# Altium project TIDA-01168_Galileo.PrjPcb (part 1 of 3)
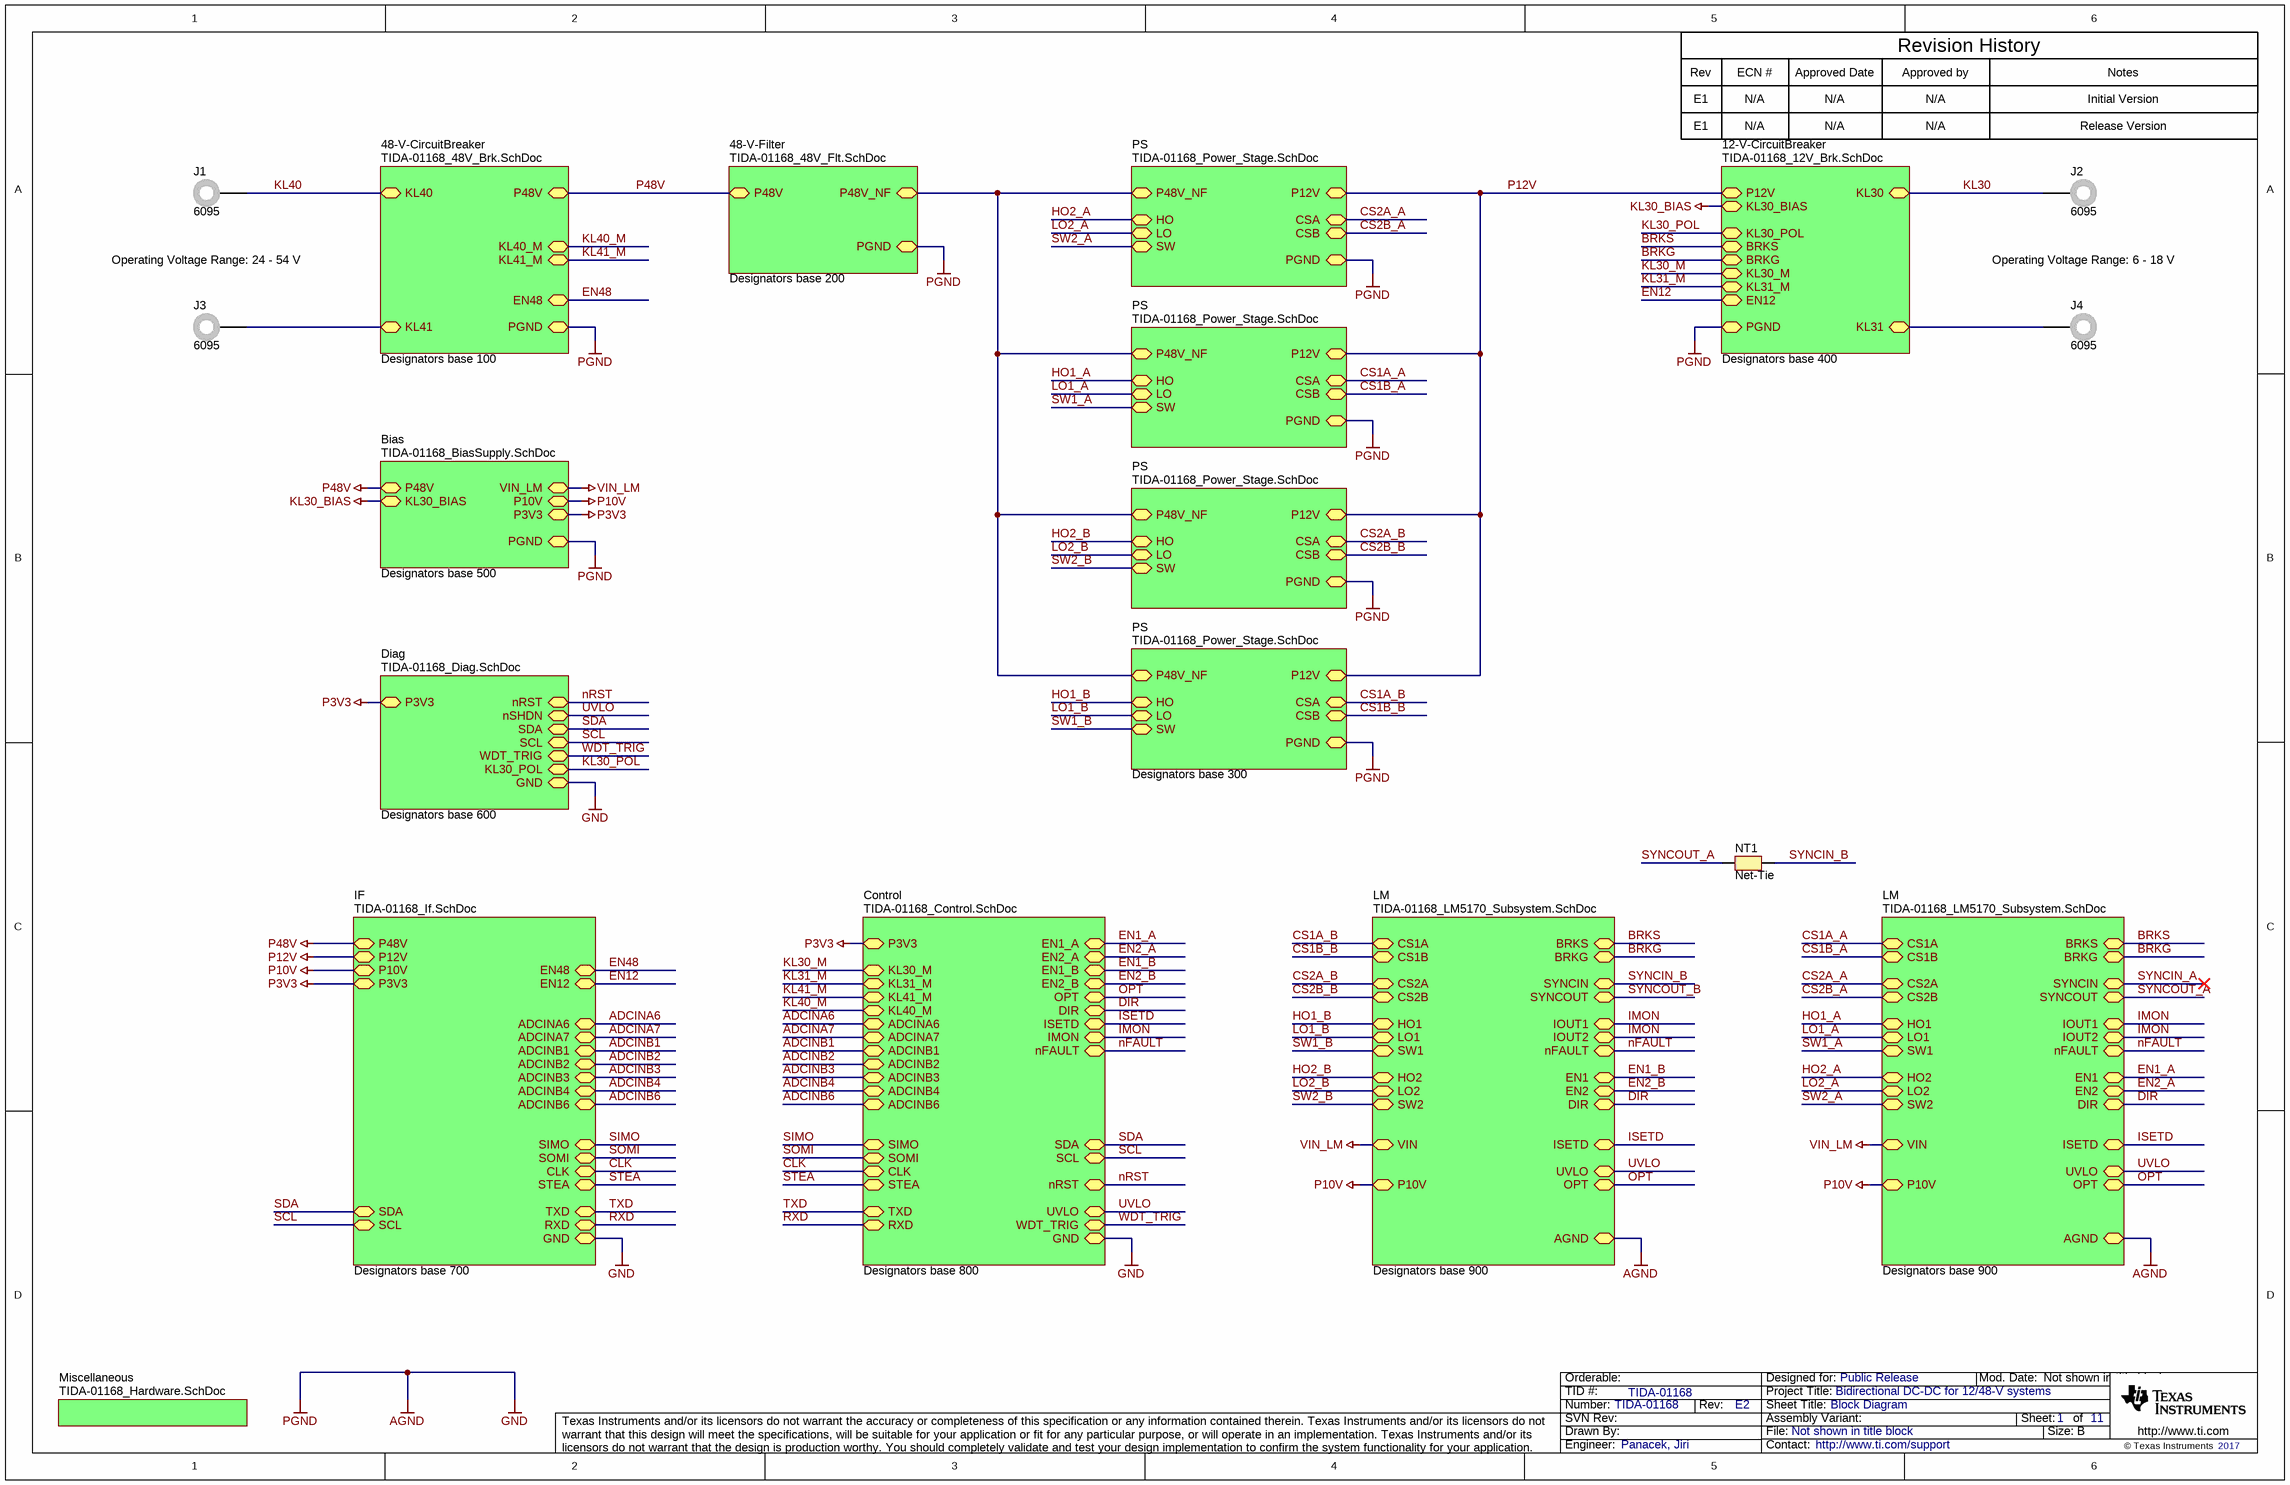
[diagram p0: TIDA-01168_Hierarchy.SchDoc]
CopyrightYear: 2017; PCB_Layout: Panacek, Jiri; PCB_Rev: E2; PRJ_Customer: Public Release; PRJ_Engineer: Panacek, Jiri; PRJ_Number: TIDA-01168; PRJ_Title: Bidirectional DC-DC for 12/48-V systems; SCH_Rev: E2; TechSupport: http://www.ti.com/support; TID: TIDA-01168
11 sheets, 477 parts. Net scope: hierarchical (ports join the sheet entries above them; power ports are global).
Board file: TIDA-01168_PCB.PcbDoc
Sheets:
  TIDA-01168_Hierarchy.SchDoc
    PS = TIDA-01168_Power_Stage.SchDoc
    Miscellaneous = TIDA-01168_Hardware.SchDoc
    48-V-CircuitBreaker = TIDA-01168_48V_Brk.SchDoc
    12-V-CircuitBreaker = TIDA-01168_12V_Brk.SchDoc
    Diag = TIDA-01168_Diag.SchDoc
    Control = TIDA-01168_Control.SchDoc
    LM = TIDA-01168_LM5170_Subsystem.SchDoc
    Bias = TIDA-01168_BiasSupply.SchDoc
    PS = TIDA-01168_Power_Stage.SchDoc
    PS = TIDA-01168_Power_Stage.SchDoc
    PS = TIDA-01168_Power_Stage.SchDoc
    LM = TIDA-01168_LM5170_Subsystem.SchDoc
    IF = TIDA-01168_If.SchDoc
    48-V-Filter = TIDA-01168_48V_Flt.SchDoc

## Sheet TIDA-01168_Hierarchy.SchDoc: Block Diagram
size 431 x 279 mm; Date: Not shown in title block; ApprovedBy: Not shown in title block; CheckedBy: Not shown in title block; Author: Not shown in title block; CompanyName: Not shown in title block; Engineer: Not shown in title block; Organization: Not shown in title block; Address1: Not shown in title block; Address2: Not shown in title block; Address3: Not shown in title block; Address4: Not shown in title block; DocumentNumber: 1; Revision: Use project parameter SCH_Rev; SheetNumber: 1; SheetTotal: 11; PageSetup: Record=PageOptions¦CenterHorizontal=True¦CenterVertical=True¦PrintScale=0.64¦XCorrection=1.00¦YCorrection=1.00¦PrintKind=0¦BorderSize=5000000¦LeftOffset=0¦BottomOffset=0¦Orientation=2¦PaperLength=1000¦PaperWidth=1000¦Scale=100¦PaperSource=15¦PrintQuality=600¦MediaType=1¦DitherType=10¦PrintScaleMode=1¦PaperKind=Letter

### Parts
J1  6095  [Keystone_6095]
J2  6095  [Keystone_6095]
J3  6095  [Keystone_6095]
J4  6095  [Keystone_6095]
NT1  Net-Tie  [Net-Tie_10mil]  (net tie, no BOM)

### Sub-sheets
12-V-CircuitBreaker = TIDA-01168_12V_Brk.SchDoc: P12V, PGND, KL31, KL30, BRKS, BRKG, KL30_BIAS, EN12, KL30_POL, KL30_M, KL31_M
48-V-CircuitBreaker = TIDA-01168_48V_Brk.SchDoc: KL40, KL41, PGND, P48V, EN48, KL40_M, KL41_M
48-V-Filter = TIDA-01168_48V_Flt.SchDoc: P48V_NF, P48V, PGND
Bias = TIDA-01168_BiasSupply.SchDoc: P48V, KL30_BIAS, VIN_LM, P3V3, P10V, PGND
Control = TIDA-01168_Control.SchDoc: SCL, SDA, EN1_A, EN2_A, EN1_B, EN2_B, OPT, DIR, ISETD, IMON, nFAULT, TXD, RXD, P3V3, nRST, GND, UVLO, WDT_TRIG, ADCINA6, ADCINA7, ADCINB1, ADCINB2, ADCINB3, ADCINB4, ADCINB6, SIMO, SOMI, CLK, STEA, KL41_M, KL40_M, KL31_M, KL30_M
Diag = TIDA-01168_Diag.SchDoc: SCL, SDA, nRST, P3V3, GND, KL30_POL, nSHDN, WDT_TRIG
IF = TIDA-01168_If.SchDoc: EN48, EN12, TXD, RXD, GND, P3V3, STEA, CLK, SOMI, SIMO, ADCINB6, ADCINB4, ADCINB3, ADCINB2, ADCINB1, ADCINA7, ADCINA6, SDA, SCL, P48V, P12V, P10V
LM = TIDA-01168_LM5170_Subsystem.SchDoc: CS1A, CS1B, HO1, SW2, SW1, BRKS, BRKG, UVLO, VIN, nFAULT, IOUT2, IOUT1, EN2, EN1, SYNCOUT, SYNCIN, ISETD, DIR, AGND, CS2A, CS2B, HO2, LO1, LO2, P10V, OPT
LM = TIDA-01168_LM5170_Subsystem.SchDoc: CS1A, CS1B, HO1, SW2, SW1, BRKS, BRKG, UVLO, VIN, nFAULT, IOUT2, IOUT1, EN2, EN1, SYNCOUT, SYNCIN, ISETD, DIR, AGND, CS2A, CS2B, HO2, LO1, LO2, P10V, OPT
Miscellaneous = TIDA-01168_Hardware.SchDoc: no entries
PS = TIDA-01168_Power_Stage.SchDoc: P48V_NF, P12V, PGND, HO, CSA, LO, SW, CSB
PS = TIDA-01168_Power_Stage.SchDoc: P48V_NF, P12V, PGND, HO, CSA, LO, SW, CSB
PS = TIDA-01168_Power_Stage.SchDoc: P48V_NF, P12V, PGND, HO, CSA, LO, SW, CSB
PS = TIDA-01168_Power_Stage.SchDoc: P48V_NF, P12V, PGND, HO, CSA, LO, SW, CSB

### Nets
CS1B_A: sheet PS/P12V, sheet PS/CSB, sheet 12-V-CircuitBreaker/P12V, sheet LM/CS1B, sheet LM/CS2B, sheet PS/P12V, sheet PS/CSB, sheet PS/P12V, sheet PS/CSB, sheet PS/P12V, sheet PS/CSB, sheet LM/CS1B, sheet LM/CS2B, sheet IF/P12V  [also labelled CS1B_B, CS2B_A, CS2B_B, P12V]
GND: J3.1 J4.1 ; sheet PS/PGND, sheet 48-V-CircuitBreaker/KL41, sheet 48-V-CircuitBreaker/PGND, sheet 12-V-CircuitBreaker/PGND, sheet 12-V-CircuitBreaker/KL31, sheet Diag/GND, sheet Control/GND, sheet LM/AGND, sheet Bias/PGND, sheet PS/PGND, sheet PS/PGND, sheet PS/PGND, sheet LM/AGND, sheet IF/GND, sheet 48-V-Filter/PGND  [also labelled AGND, PGND]
KL30_BIAS: sheet 12-V-CircuitBreaker/KL30_BIAS, sheet Bias/KL30_BIAS
P3V3: sheet Diag/P3V3, sheet Control/P3V3, sheet Bias/P3V3, sheet IF/P3V3
P10V: sheet LM/P10V, sheet Bias/P10V, sheet LM/P10V, sheet IF/P10V
P48V: sheet 48-V-CircuitBreaker/P48V, sheet Bias/P48V, sheet IF/P48V, sheet 48-V-Filter/P48V
VIN_LM: sheet LM/VIN, sheet Bias/VIN_LM, sheet LM/VIN
ADCINA6: sheet Control/ADCINA6, sheet IF/ADCINA6
ADCINA7: sheet Control/ADCINA7, sheet IF/ADCINA7
ADCINB1: sheet Control/ADCINB1, sheet IF/ADCINB1
ADCINB2: sheet Control/ADCINB2, sheet IF/ADCINB2
ADCINB3: sheet Control/ADCINB3, sheet IF/ADCINB3
ADCINB4: sheet Control/ADCINB4, sheet IF/ADCINB4
ADCINB6: sheet Control/ADCINB6, sheet IF/ADCINB6
BRKG: sheet 12-V-CircuitBreaker/BRKG, sheet LM/BRKG, sheet LM/BRKG
BRKS: sheet 12-V-CircuitBreaker/BRKS, sheet LM/BRKS, sheet LM/BRKS
CLK: sheet Control/CLK, sheet IF/CLK
CS1A_A: sheet LM/CS1A, sheet PS/CSA
CS1A_B: sheet PS/CSA, sheet LM/CS1A
CS2A_A: sheet PS/CSA, sheet LM/CS2A
CS2A_B: sheet PS/CSA, sheet LM/CS2A
DIR: sheet Control/DIR, sheet LM/DIR, sheet LM/DIR
EN1_A: sheet Control/EN1_A, sheet LM/EN1  [project net EN1]
EN1_B: sheet Control/EN1_B, sheet LM/EN1  [project net EN1]
EN2_A: sheet Control/EN2_A, sheet LM/EN2  [project net EN2]
EN2_B: sheet Control/EN2_B, sheet LM/EN2  [project net EN2]
EN12: sheet 12-V-CircuitBreaker/EN12, sheet IF/EN12
EN48: sheet 48-V-CircuitBreaker/EN48, sheet IF/EN48
HO1_A: sheet LM/HO1, sheet PS/HO
HO1_B: sheet PS/HO, sheet LM/HO1
HO2_A: sheet PS/HO, sheet LM/HO2
HO2_B: sheet PS/HO, sheet LM/HO2
IMON: sheet Control/IMON, sheet LM/IOUT2, sheet LM/IOUT1, sheet LM/IOUT2, sheet LM/IOUT1
ISETD: sheet Control/ISETD, sheet LM/ISETD, sheet LM/ISETD
KL30: J2.1 ; sheet 12-V-CircuitBreaker/KL30
KL30_M: sheet 12-V-CircuitBreaker/KL30_M, sheet Control/KL30_M
KL30_POL: sheet 12-V-CircuitBreaker/KL30_POL, sheet Diag/KL30_POL
KL31_M: sheet 12-V-CircuitBreaker/KL31_M, sheet Control/KL31_M
KL40: J1.1 ; sheet 48-V-CircuitBreaker/KL40
KL40_M: sheet 48-V-CircuitBreaker/KL40_M, sheet Control/KL40_M
KL41_M: sheet 48-V-CircuitBreaker/KL41_M, sheet Control/KL41_M
LO1_A: sheet LM/LO1, sheet PS/LO
LO1_B: sheet PS/LO, sheet LM/LO1
LO2_A: sheet PS/LO, sheet LM/LO2
LO2_B: sheet PS/LO, sheet LM/LO2
nFAULT: sheet Control/nFAULT, sheet LM/nFAULT, sheet LM/nFAULT
nRST: sheet Diag/nRST, sheet Control/nRST
OPT: sheet Control/OPT, sheet LM/OPT, sheet LM/OPT
P48V_NF: sheet PS/P48V_NF, sheet PS/P48V_NF, sheet PS/P48V_NF, sheet PS/P48V_NF, sheet 48-V-Filter/P48V_NF
RXD: sheet Control/RXD, sheet IF/RXD
SCL: sheet Diag/SCL, sheet Control/SCL, sheet IF/SCL
SDA: sheet Diag/SDA, sheet Control/SDA, sheet IF/SDA
SIMO: sheet Control/SIMO, sheet IF/SIMO
SOMI: sheet Control/SOMI, sheet IF/SOMI
STEA: sheet Control/STEA, sheet IF/STEA
SW1_A: sheet LM/SW1, sheet PS/SW
SW1_B: sheet PS/SW, sheet LM/SW1
SW2_A: sheet PS/SW, sheet LM/SW2
SW2_B: sheet PS/SW, sheet LM/SW2
SYNCIN_B: NT1.2 ; sheet LM/SYNCIN
SYNCOUT_A: NT1.1 ; sheet LM/SYNCOUT
TXD: sheet Control/TXD, sheet IF/TXD
UVLO: sheet Diag/nSHDN, sheet Control/UVLO, sheet LM/UVLO, sheet LM/UVLO
WDT_TRIG: sheet Diag/WDT_TRIG, sheet Control/WDT_TRIG

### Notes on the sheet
- Rev
- E1
- ECN #
- N/A
- Approved Date
- Approved by
- Revision History
- Notes
- Initial Version
- Release Version
- Operating Voltage Range: 24 - 54 V
- Designators base 200
- Operating Voltage Range: 6 - 18 V
- Designators base 100
- Designators base 400
- Designators base 500
- Designators base 600
- Designators base 300
- Designators base 700
- Designators base 800
- Designators base 900

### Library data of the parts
J1-J4 = 6095: Standard Banana Jack, Uninsulated; Manufacturer: Keystone; CompType: Connector; SymbolCreator: a0412235
NT1 = Net-Tie: Single point connection between nets.; SymbolCreator: codlsc

## Sheet TIDA-01168_Power_Stage.SchDoc: Power Stage
size 431 x 279 mm; Date: Not shown in title block; ApprovedBy: Not shown in title block; CheckedBy: Not shown in title block; Author: Not shown in title block; CompanyName: Not shown in title block; Engineer: Not shown in title block; Organization: Not shown in title block; Address1: Not shown in title block; Address2: Not shown in title block; Address3: Not shown in title block; Address4: Not shown in title block; DocumentNumber: 4; Revision: Use project parameter SCH_Rev; SheetNumber: 4; SheetTotal: 11; PageSetup: Record=PageOptions¦CenterHorizontal=True¦CenterVertical=True¦PrintScale=0.62¦XCorrection=1.00¦YCorrection=1.00¦PrintKind=0¦BorderSize=5000000¦LeftOffset=0¦BottomOffset=0¦Orientation=2¦PaperLength=1000¦PaperWidth=1000¦Scale=100¦PaperSource=15¦PrintQuality=600¦MediaType=1¦DitherType=10¦PrintScaleMode=1¦PaperKind=Letter
Used 4 times, as channels PS, PS, PS, PS. Parts and nets are listed once, with the designators drawn on the sheet.
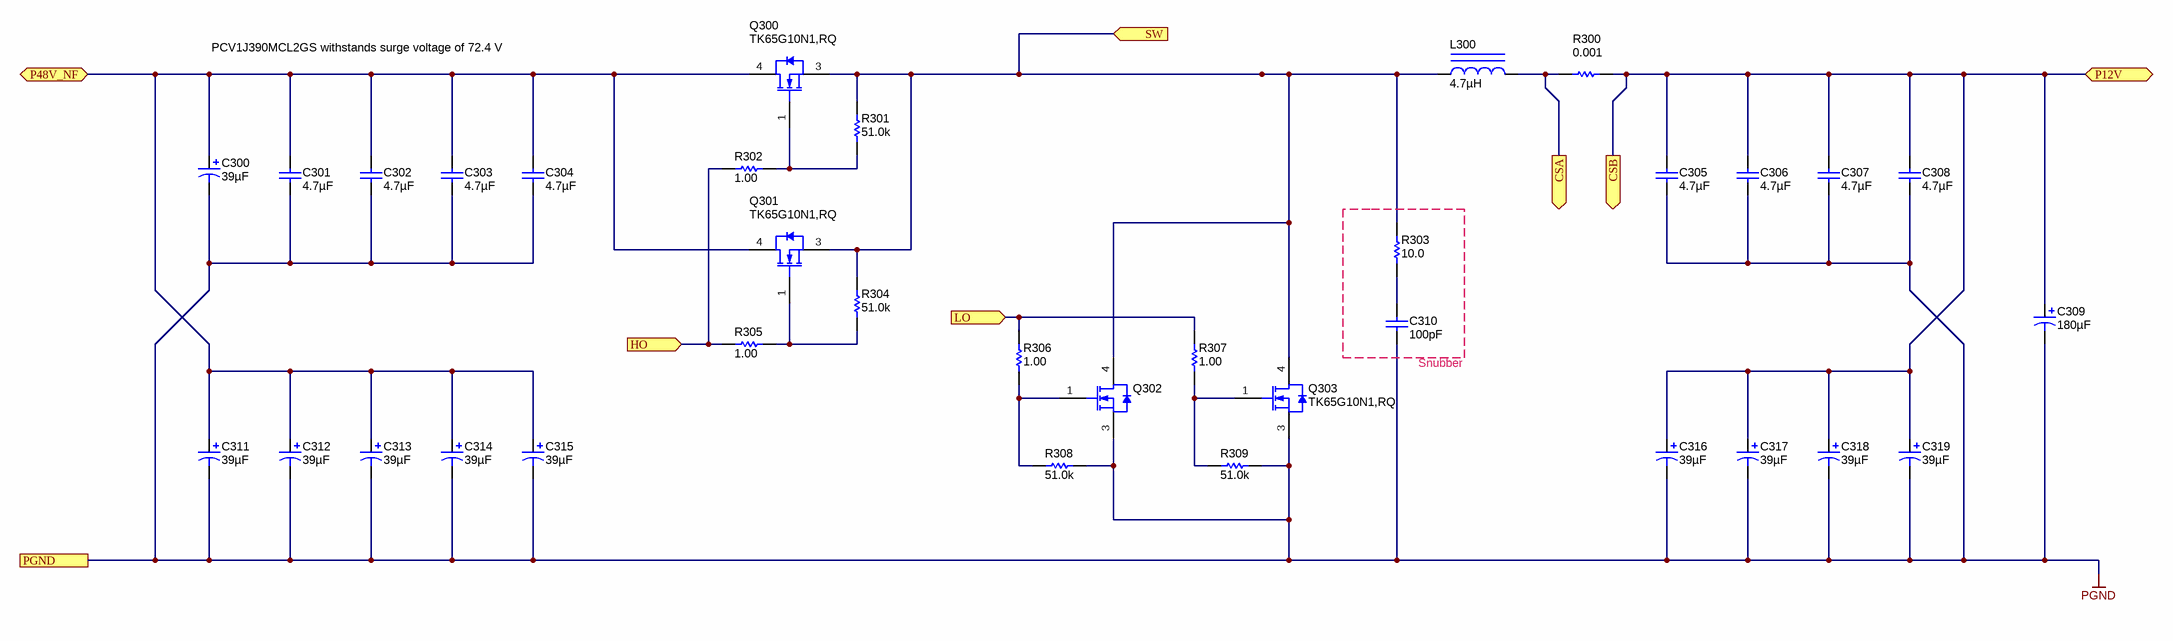
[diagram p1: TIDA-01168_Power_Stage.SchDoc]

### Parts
C300  ValueDisplayed: 39µF  [PCV_800x1200]  (hidden comment: PCV1J390MCL2GS)
C301  ValueDisplayed: 4.7µF  [2220_250]  (hidden comment: CGA9N2X7R2A475M230KA)
C302  ValueDisplayed: 4.7µF  [2220_250]  (hidden comment: CGA9N2X7R2A475M230KA)
C303  ValueDisplayed: 4.7µF  [2220_250]  (hidden comment: CGA9N2X7R2A475M230KA)
C304  ValueDisplayed: 4.7µF  [2220_250]  (hidden comment: CGA9N2X7R2A475M230KA)
C305  ValueDisplayed: 4.7µF  [2220_250]  (hidden comment: CGA9N2X7R2A475M230KA)
C306  ValueDisplayed: 4.7µF  [2220_250]  (hidden comment: CGA9N2X7R2A475M230KA)
C307  ValueDisplayed: 4.7µF  [2220_250]  (hidden comment: CGA9N2X7R2A475M230KA)
C308  ValueDisplayed: 4.7µF  [2220_250]  (hidden comment: CGA9N2X7R2A475M230KA)
C309  ValueDisplayed: 180µF  [UCZ_1250x1350]  (hidden comment: UCZ1J181MNQ1MS)
C310  ValueDisplayed: 100pF  [0805_HV]  (hidden comment: GCM2165C2A101JA16D)
C311  ValueDisplayed: 39µF  [PCV_800x1200]  (hidden comment: PCV1J390MCL2GS)
C312  ValueDisplayed: 39µF  [PCV_800x1200]  (hidden comment: PCV1J390MCL2GS)
C313  ValueDisplayed: 39µF  [PCV_800x1200]  (hidden comment: PCV1J390MCL2GS)
C314  ValueDisplayed: 39µF  [PCV_800x1200]  (hidden comment: PCV1J390MCL2GS)
C315  ValueDisplayed: 39µF  [PCV_800x1200]  (hidden comment: PCV1J390MCL2GS)
C316  ValueDisplayed: 39µF  [PCV_800x1200]  (hidden comment: PCV1J390MCL2GS)
C317  ValueDisplayed: 39µF  [PCV_800x1200]  (hidden comment: PCV1J390MCL2GS)
C318  ValueDisplayed: 39µF  [PCV_800x1200]  (hidden comment: PCV1J390MCL2GS)
C319  ValueDisplayed: 39µF  [PCV_800x1200]  (hidden comment: PCV1J390MCL2GS)
L300  ValueDisplayed: 4.7µH  [SER2915L]  (hidden comment: SER2915L-472KL)
Q300  TK65G10N1,RQ  [DDPAK]
Q301  TK65G10N1,RQ  [DDPAK]
Q302  TK65G10N1,RQ  [DDPAK]  (value not drawn)
Q303  TK65G10N1,RQ  [DDPAK]
R300  ValueDisplayed: 0.001  [3921_105]  (hidden comment: PSR400ITQFH1L00)
R301  ValueDisplayed: 51.0k  [0603]  (hidden comment: RC0603FR-0751KL)
R302  ValueDisplayed: 1.00  [0603]  (hidden comment: RC0603FR-071RL)
R303  ValueDisplayed: 10.0  [1218]  (hidden comment: CRCW121810R0FKEK)
R304  ValueDisplayed: 51.0k  [0603]  (hidden comment: RC0603FR-0751KL)
R305  ValueDisplayed: 1.00  [0603]  (hidden comment: RC0603FR-071RL)
R306  ValueDisplayed: 1.00  [0603]  (hidden comment: RC0603FR-071RL)
R307  ValueDisplayed: 1.00  [0603]  (hidden comment: RC0603FR-071RL)
R308  ValueDisplayed: 51.0k  [0603]  (hidden comment: RC0603FR-0751KL)
R309  ValueDisplayed: 51.0k  [0603]  (hidden comment: RC0603FR-0751KL)

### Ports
CSA, CSB, HO, LO, P12V, P48V_NF, PGND, SW

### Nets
PGND: C300.2(-) C301.2 C302.2 C303.2 C304.2 C305.2 C306.2 C307.2 C308.2 C309.2(-) C310.2 C311.2(-) C312.2(-) C313.2(-) C314.2(-) C315.2(-) C316.2(-) C317.2(-) C318.2(-) C319.2(-) Q302.3(S) Q303.3(S) R308.1 R309.1 ; port PGND
CSA: L300.1 R300.1 ; port CSA
CSB: C305.1 C306.1 C307.1 C308.1 C309.1(+) C316.1(+) C317.1(+) C318.1(+) C319.1(+) R300.2 ; port P12V, port CSB
HO: R302.1 R305.1 ; port HO
LO: R306.2 R307.2 ; port LO
P48V_NF: C300.1(+) C301.1 C302.1 C303.1 C304.1 C311.1(+) C312.1(+) C313.1(+) C314.1(+) C315.1(+) Q300.4(D) Q301.4(D) ; port P48V_NF
SW: L300.2 Q300.3(S) Q301.3(S) Q302.4(D) Q303.4(D) R301.2 R303.2 R304.2 ; port SW
NetC310_1: C310.1 R303.1
NetQ300_1: Q300.1(G) R301.1 R302.2
NetQ301_1: Q301.1(G) R304.1 R305.2
NetQ302_1: Q302.1(G) R306.1 R308.2
NetQ303_1: Q303.1(G) R307.1 R309.2

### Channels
PS: designators end in _PS4; ports CSA=CS2A_A CSB=CS1B_A HO=HO2_A LO=LO2_A P12V=CS1B_A P48V_NF=P48V_NF PGND=GND SW=SW2_A
PS: designators end in _PS3; ports CSA=CS1A_A CSB=CS1B_A HO=HO1_A LO=LO1_A P12V=CS1B_A P48V_NF=P48V_NF PGND=GND SW=SW1_A
PS: designators end in _PS2; ports CSA=CS2A_B CSB=CS1B_A HO=HO2_B LO=LO2_B P12V=CS1B_A P48V_NF=P48V_NF PGND=GND SW=SW2_B
PS: designators end in _PS1; ports CSA=CS1A_B CSB=CS1B_A HO=HO1_B LO=LO1_B P12V=CS1B_A P48V_NF=P48V_NF PGND=GND SW=SW1_B

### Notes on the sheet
- PCV1J390MCL2GS withstands surge voltage of 72.4 V
- (near C310) Snubber

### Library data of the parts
C300 = PCV1J390MCL2GS: CAP, Aluminum Polymer, 39 µF, 63 V, +/- 20%, 0.029 ohm, AEC-Q200 Grade 2, D8xL12mm SMD; Manufacturer: Nichicon; Polarized: Y; CompType: Capacitor; Value: 39uF; U/M: EA; Cap_F: 0.000039; Tolerance_%: 20; ESR_ohm: 0.029; VDC_V: 63; Value2: 63V; IRMS_A: 3.4; TaMin_C: -55; TaMax_C: 105; Cap_Case: 8x12mm; AEC Category: Q200; AEC Grade: 2
C301-C308 = CGA9N2X7R2A475M230KA: CAP, CERM, 4.7 µF, 100 V, +/- 20%, X7R, AEC-Q200 Grade 1,; Manufacturer: TDK; Polarized: N; CompType: Capacitor; Value: 4.7uF; U/M: EA; Cap_F: 0.0000047; Tolerance_%: 20; Value1: Unknown; VDC_V: 100; Value2: 100V; TaMin_C: -55; TaMax_C: 125; Cap_Case: 2220; SizeArea_mm2: 28.5; SizeAreaWB_mm2: 53.9; SizeX_mm: 5.7; SizeY_mm: 5; SizeZ_mm: 2.5; AEC Category: Q200; AEC Qualified: Y; AEC Grade: 1
C309 = UCZ1J181MNQ1MS: CAP, AL, 180 µF, 63 V, +/- 20%, 0.2 ohm, AEC-Q200 Grade 1, SMD; Manufacturer: Nichicon; Polarized: Y; CompType: Capacitor; Value: 180uF; U/M: EA; Cap_F: 0.00018; Tolerance_%: 20; Value1: 0.2 ohm; VDC_V: 63; Value2: 63V; ESR_ohm: 0.2; IRMS_A: 1; TaMin_C: -40; TaMax_C: 125; Cap_Case: 12.5x13.5mm; AEC Category: Q200
C310 = GCM2165C2A101JA16D: CAP, CERM, 100 pF, 100 V, +/- 5%, C0G/NP0, AEC-Q200 Grade 1, 0805; Manufacturer: MuRata; Polarized: N; CompType: Capacitor; Value: 100pF; U/M: EA; Cap_F: 0.0000000001; Tolerance_%: 5; Value1: Unknown; VDC_V: 100; Value2: 100V; TaMin_C: -55; TaMax_C: 105; Cap_Case: 0805; SizeArea_mm2: 2.5; SizeAreaWB_mm2: 6.75; SizeX_mm: 2; SizeY_mm: 1.25; SizeZ_mm: 1.45; AEC Category: Q200; AEC Qualified: Y; AEC Grade: 1
C311-C319 = PCV1J390MCL2GS: CAP, Aluminum Polymer, 39 µF, 63 V, +/- 20%, 0.029 ohm, AEC-Q200 Grade 2, D8xL12mm SMD; Manufacturer: Nichicon; Polarized: Y; CompType: Capacitor; Value: 39uF; U/M: EA; Cap_F: 0.000039; Tolerance_%: 20; VDC_V: 63; Value2: 63V; ESR_ohm: 0.029; IRMS_A: 3.4; TaMin_C: -55; TaMax_C: 105; Cap_Case: 8x12mm; AEC Category: Q200; AEC Grade: 2
L300 = SER2915L-472KL: Inductor, Shielded E Core, Ferrite, 4.7 µH, 30 A, 0.0015 ohm, SMD; Manufacturer: Coilcraft; Value: 4.7uH; Ind_H: 4.7E-6; Imax_A: 30; Irms: 30A @ 40C rise; Isat: 39A @ 30% inductance drop; DCR_ohm: 0.0015; Value2: 30A; AEC Category: Q200
Q300-Q303 = TK65G10N1,RQ: MOSFET, N-CH, 100 V, 65 A, DDPAK; Manufacturer: Toshiba; Alternate Manufacturer: None; U/M: EA; ChType: N; Value: 100V; VdsMax_V: 100; Value1: ? ohm; Value2: 81 nC; QgTyp_nC: 81; Vgs_V: 20; IdsMax_A: 65; SizeAreaWB_mm2: 209.6992; SizeArea_mm2: 154.8892; SizeX_mm: 15.245; SizeY_mm: 10.16; SizeZ_mm: 4.445; AEC Category: Q101
R300 = PSR400ITQFH1L00: RES, 0.001, 1%, 4 W, AEC-Q200 Grade 0, 10x5.2mm; Manufacturer: Rohm; CompType: Resistor; Value: 0.001; Value_Code: 1L000; Tolerance_%: 1; Power_W: 4; Value2: 4W; TempCo: 75 ppm/C; SizeArea_mm2: 52; SizeAreaWB_mm2: 86.4; SizeX_mm: 10; SizeY_mm: 5.2; SizeZ_mm: 1.05; EIA_Code: E96; U/M: EA; AEC Category: Q200; AEC Qualified: Y; AEC Grade: 0
R301 R304 R308 R309 = RC0603FR-0751KL: RES, 51.0 k, 1%, 0.1 W, 0603; Manufacturer: Yageo America; CompType: Resistor; Value: 51.0k; Res_ohm: 51000; Value_Code: 51k0; Tolerance_%: 1; Power_W: 0.1; Value2: 0.1W; VDC_V: 150; TempCo: 200 ppm/C; SizeArea_mm2: 1.28; SizeX_mm: 1.6; SizeY_mm: 0.8; U/M: EA; AEC Category: Q200
R302 R305-R307 = RC0603FR-071RL: RES, 1.00, 1%, 0.1 W, 0603; Manufacturer: Yageo America; CompType: Resistor; Value: 1.00; Res_ohm: 1; Value_Code: 1R00; Power_W: 0.1; Value2: 0.1W; VDC_V: 150; TempCo: 200 ppm/C; SizeArea_mm2: 1.28; SizeX_mm: 1.6; SizeY_mm: 0.8; EIA_Code: E96; U/M: EA; AEC Category: Q200
R303 = CRCW121810R0FKEK: RES, 10.0, 1%, 1 W, 1218; Manufacturer: Vishay-Dale; CompType: Resistor; Value: 10.0; Res_ohm: 10; Value_Code: 10R0; Tolerance_%: 1; Value2: 1W; VDC_V: 200; TempCo: 100 ppm/C; SizeArea_mm2: 14.72; SizeAreaWB_mm2: 23.52; SizeX_mm: 3.2; SizeY_mm: 4.6; SizeZ_mm: 0.6; EIA_Code: E96; U/M: EA; AEC Category: Q200

## Sheet TIDA-01168_Hardware.SchDoc
size 431 x 279 mm; Date: Not shown in title block; ApprovedBy: Not shown in title block; CheckedBy: Not shown in title block; Author: Not shown in title block; CompanyName: Not shown in title block; Engineer: Not shown in title block; Organization: Not shown in title block; Address1: Not shown in title block; Address2: Not shown in title block; Address3: Not shown in title block; Address4: Not shown in title block; DocumentNumber: 11; Revision: Use project parameter SCH_Rev; SheetNumber: 11; SheetTotal: 11; PageSetup: Record=PageOptions¦CenterHorizontal=True¦CenterVertical=True¦PrintScale=1.00¦XCorrection=1.00¦YCorrection=1.00¦PrintKind=0¦BorderSize=5000000¦LeftOffset=0¦BottomOffset=0¦Orientation=2¦PaperLength=1000¦PaperWidth=1000¦Scale=100¦PaperSource=15¦PrintQuality=600¦MediaType=1¦DitherType=10¦PaperKind=Letter¦PrintScaleMode=1
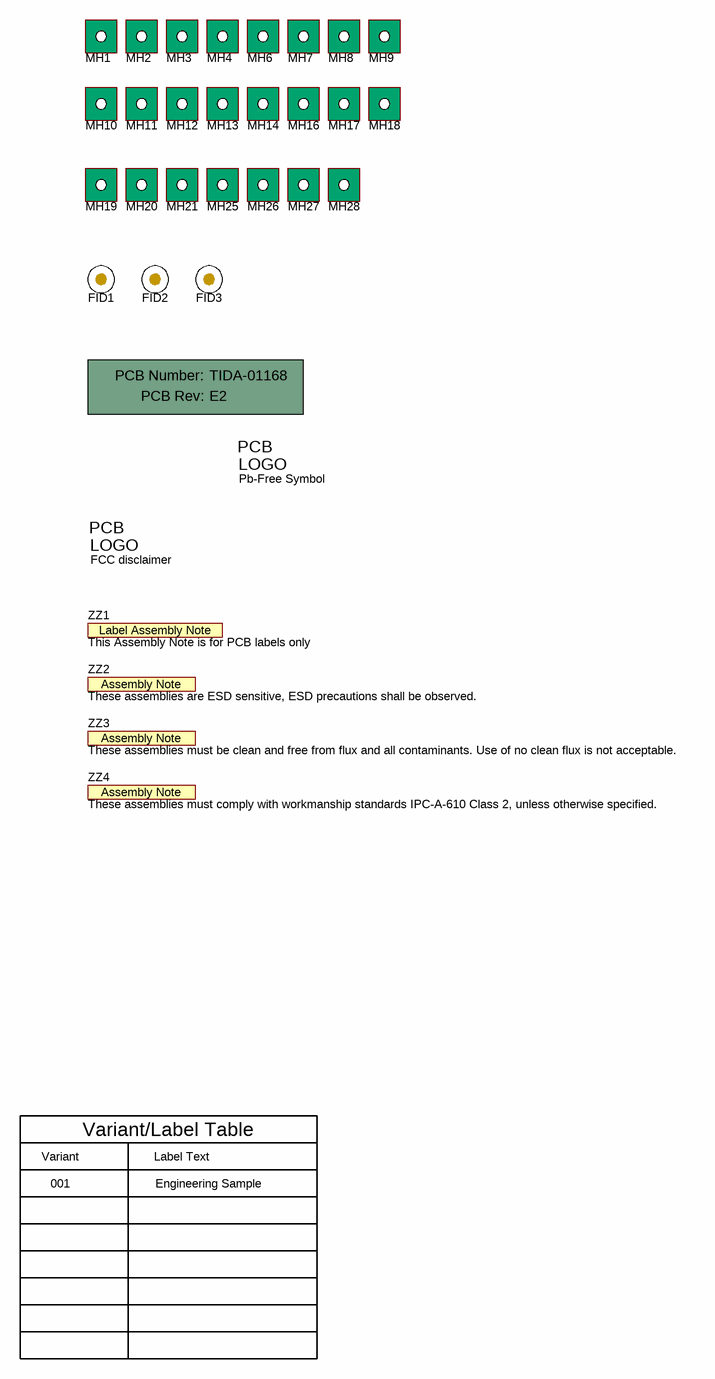
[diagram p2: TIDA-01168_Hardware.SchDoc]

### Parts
!PCB1  Printed Circuit Board  (value not drawn)  (mechanical)
FID1  Fiducial  [Fiducial10-20]  (value not drawn)
FID2  Fiducial  [Fiducial10-20]  (value not drawn)
FID3  Fiducial  [Fiducial10-20]  (value not drawn)
Logo2  Pb-Free Symbol  [Pb-Free_Overlay_Small]  (no BOM)
Logo3  FCC disclaimer  [FCC_disclaimer]  (no BOM)
MH1  MTG_NoPads  [NPTH125mil]  (value not drawn)  (no BOM)
MH2  MTG_NoPads  [NPTH125mil]  (value not drawn)  (no BOM)
MH3  MTG_NoPads  [NPTH125mil]  (value not drawn)  (no BOM)
MH4  MTG_NoPads  [NPTH125mil]  (value not drawn)  (no BOM)
MH6  MTG_NoPads  [NPTH125mil]  (value not drawn)  (no BOM)
MH7  MTG_NoPads  [NPTH125mil]  (value not drawn)  (no BOM)
MH8  MTG_NoPads  [NPTH125mil]  (value not drawn)  (no BOM)
MH9  MTG_NoPads  [NPTH125mil]  (value not drawn)  (no BOM)
MH10  MTG_NoPads  [NPTH125mil]  (value not drawn)  (no BOM)
MH11  MTG_NoPads  [NPTH125mil]  (value not drawn)  (no BOM)
MH12  MTG_NoPads  [NPTH125mil]  (value not drawn)  (no BOM)
MH13  MTG_NoPads  [NPTH125mil]  (value not drawn)  (no BOM)
MH14  MTG_NoPads  [NPTH125mil]  (value not drawn)  (no BOM)
MH16  MTG_NoPads  [NPTH125mil]  (value not drawn)  (no BOM)
MH17  MTG_NoPads  [NPTH125mil]  (value not drawn)  (no BOM)
MH18  MTG_NoPads  [NPTH125mil]  (value not drawn)  (no BOM)
MH19  MTG_NoPads  [NPTH125mil]  (value not drawn)  (no BOM)
MH20  MTG_NoPads  [NPTH125mil]  (value not drawn)  (no BOM)
MH21  MTG_NoPads  [NPTH125mil]  (value not drawn)  (no BOM)
MH25  MTG_NoPads  [NPTH125mil]  (value not drawn)  (no BOM)
MH26  MTG_NoPads  [NPTH125mil]  (value not drawn)  (no BOM)
MH27  MTG_NoPads  [NPTH125mil]  (value not drawn)  (no BOM)
MH28  MTG_NoPads  [NPTH125mil]  (value not drawn)  (no BOM)
ZZ1  This Assembly Note is for PCB labels only  [AssemblyNoteLabel]  (no BOM)
ZZ2  These assemblies are ESD sensitive, ESD precautions shall be observed.  [AssemblyNote]  (no BOM)
ZZ3  These assemblies must be clean and free from flux and all contaminants. Use of no clean flux is not acceptable.  [AssemblyNote]  (no BOM)
ZZ4  These assemblies must comply with workmanship standards IPC-A-610 Class 2, unless otherwise specified.  [AssemblyNote]  (no BOM)

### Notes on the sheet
- Variant
- Variant/Label Table
- Label Text
- 001
- Engineering Sample

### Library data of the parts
!PCB1 = PCB: Manufacturer: Any; PartNumber: TIDA-01168; SymbolCreator: a0412235
FID1-FID3 = Fiducial: Fiducial mark.  There is nothing to buy or mount.; SymbolCreator: codlsc
Logo2 = Pb-Free: SymbolCreator: a0412235
Logo3 = FCC_disclaimer: SymbolCreator: codlsc
MH1-MH4 MH6-MH14 MH16-MH21 MH25-MH28 = Mounting Hole (non-standard) No Pad: PCB Mounting Hole, No Pad; Manufacturer: Any; SymbolCreator: a0412235
ZZ1 = AssemblyNoteLabel: SymbolCreator: a0412235
ZZ2-ZZ4 = AssemblyNote: SymbolCreator: codlsc

## Sheet TIDA-01168_48V_Brk.SchDoc: 48-V Circuit Breaker
size 431 x 279 mm; Date: Not shown in title block; ApprovedBy: Not shown in title block; CheckedBy: Not shown in title block; Author: Not shown in title block; CompanyName: Not shown in title block; Engineer: Not shown in title block; Organization: Not shown in title block; Address1: Not shown in title block; Address2: Not shown in title block; Address3: Not shown in title block; Address4: Not shown in title block; DocumentNumber: 2; Revision: Use project parameter SCH_Rev; SheetNumber: 2; SheetTotal: 11; PageSetup: Record=PageOptions¦CenterHorizontal=True¦CenterVertical=True¦PrintScale=0.62¦XCorrection=1.00¦YCorrection=1.00¦PrintKind=0¦BorderSize=5000000¦LeftOffset=0¦BottomOffset=0¦Orientation=2¦PaperLength=1000¦PaperWidth=1000¦Scale=100¦PaperSource=15¦PrintQuality=600¦MediaType=1¦DitherType=10¦PrintScaleMode=1¦PaperKind=Letter
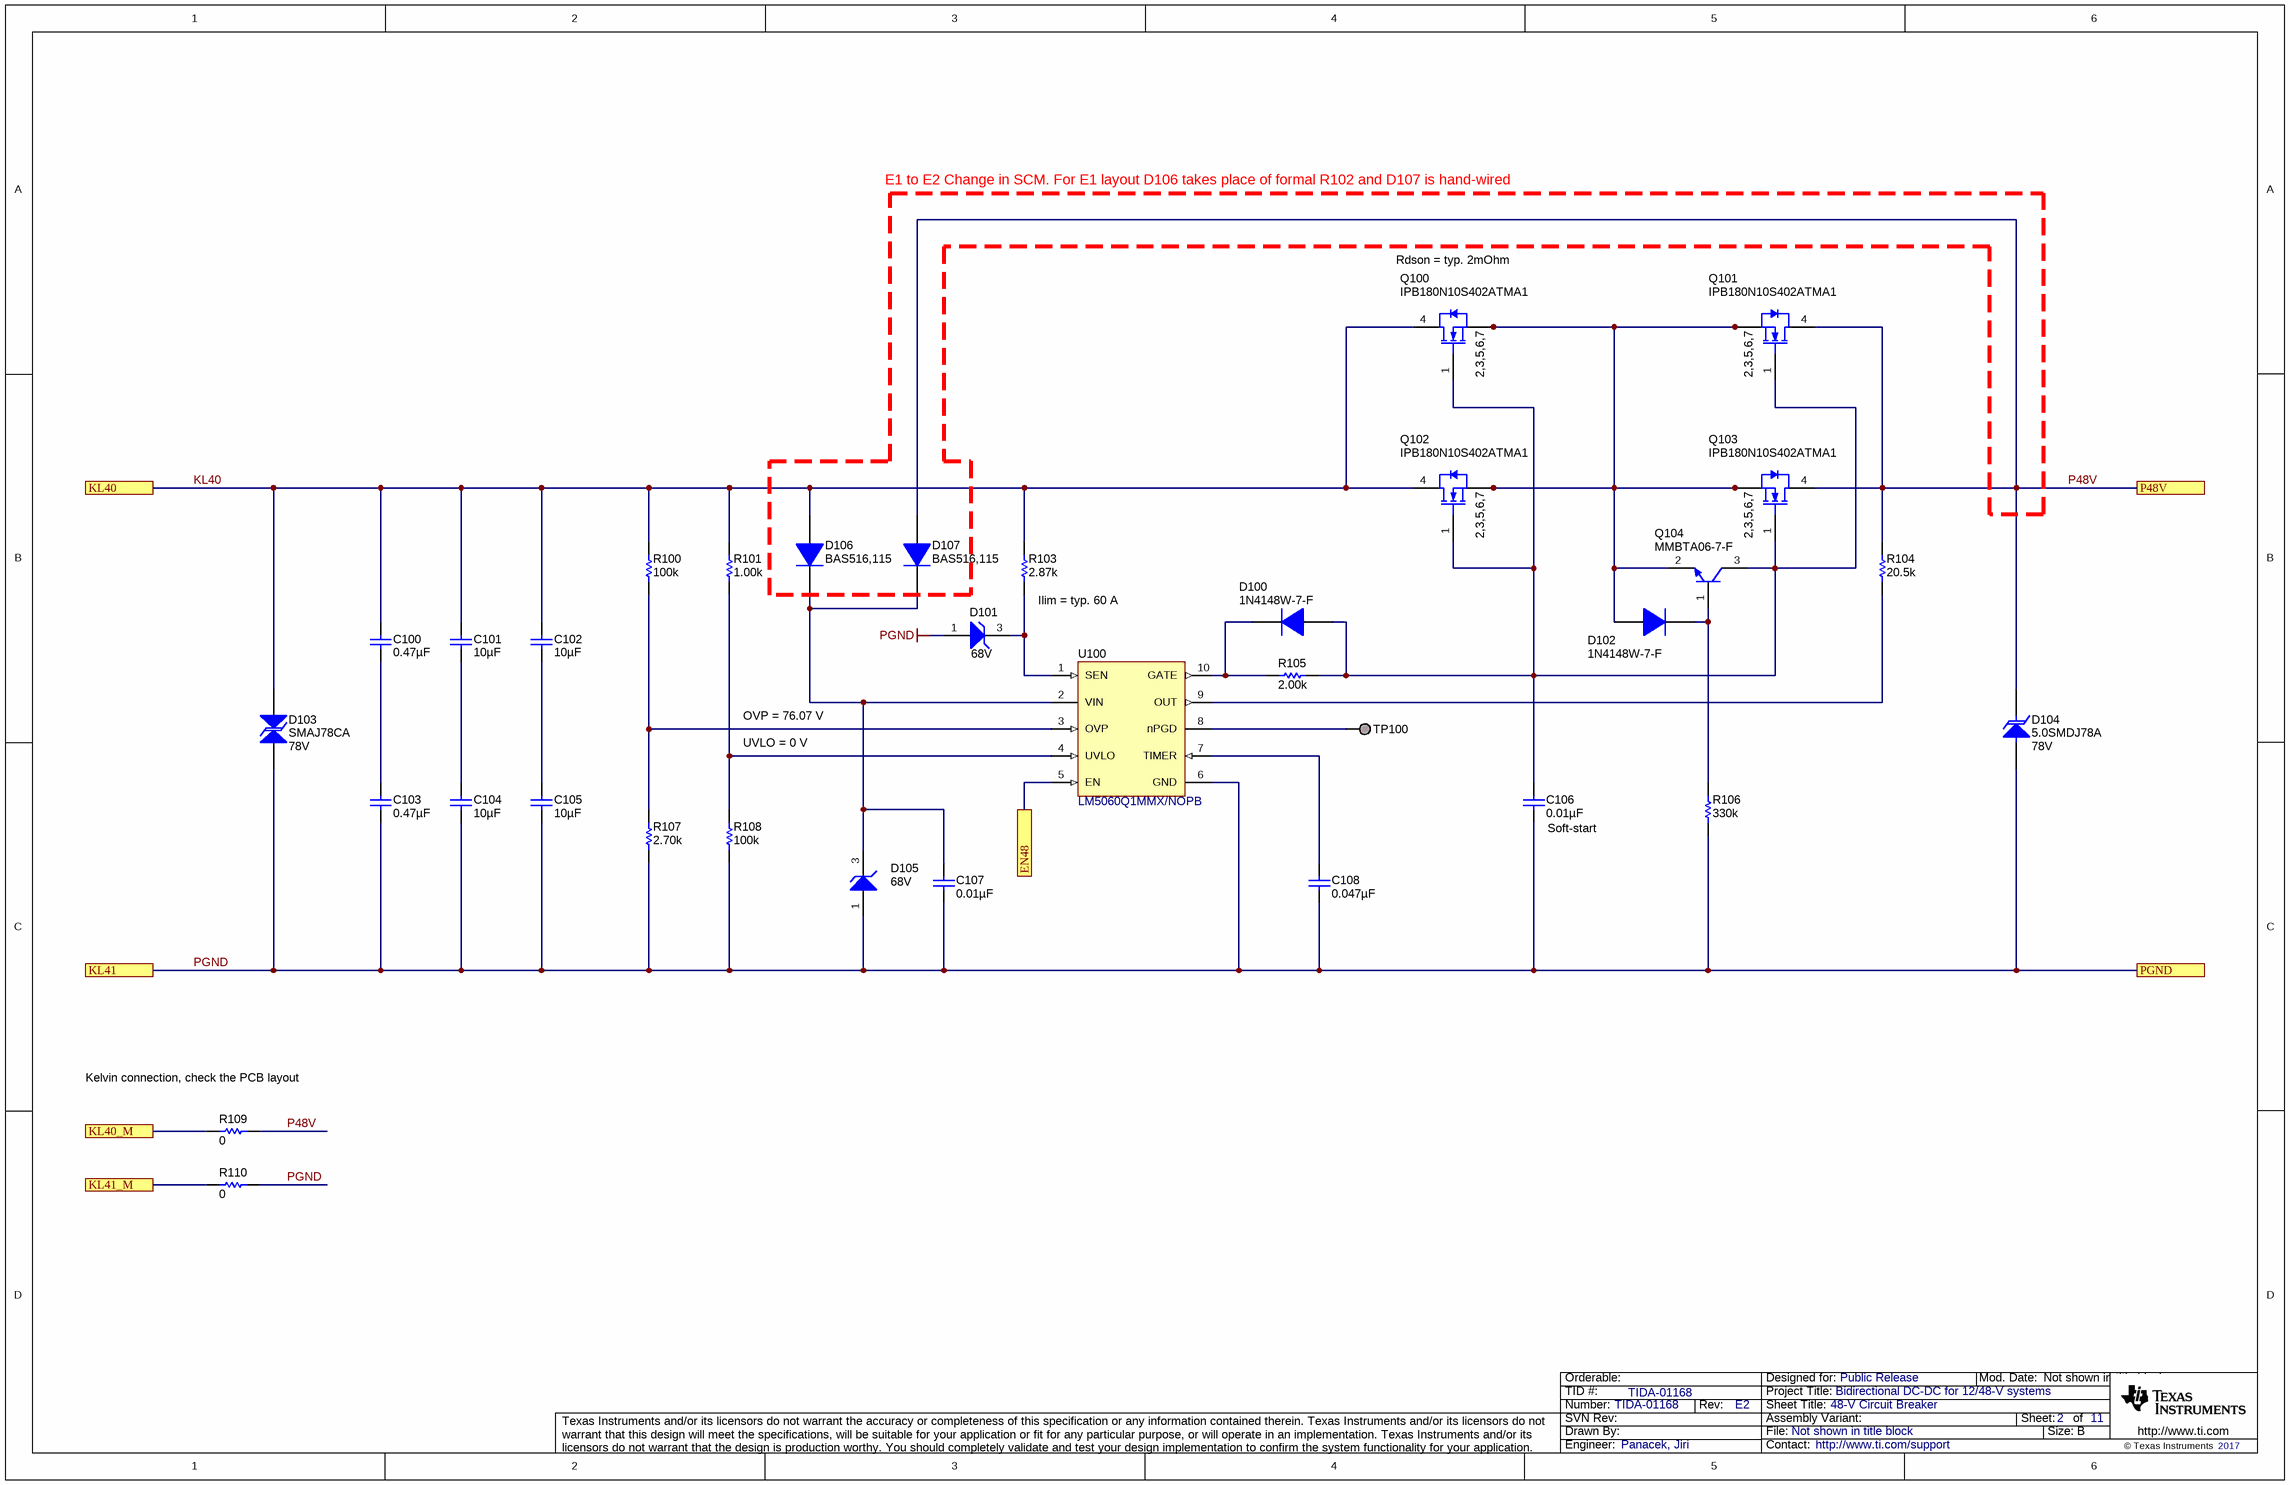
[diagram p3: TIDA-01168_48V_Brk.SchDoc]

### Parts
C100  ValueDisplayed: 0.47µF  [1210_220L]  (hidden comment: CGA6M2X7R2A474K200AA)
C101  ValueDisplayed: 10µF  [1210_280]  (hidden comment: CGA6P3X7S1H106K250AB)
C102  ValueDisplayed: 10µF  [1210_280]  (hidden comment: CGA6P3X7S1H106K250AB)
C103  ValueDisplayed: 0.47µF  [1210_220L]  (hidden comment: CGA6M2X7R2A474K200AA)
C104  ValueDisplayed: 10µF  [1210_280]  (hidden comment: CGA6P3X7S1H106K250AB)
C105  ValueDisplayed: 10µF  [1210_280]  (hidden comment: CGA6P3X7S1H106K250AB)
C106  ValueDisplayed: 0.01µF  [0805_HV]  (hidden comment: GRM21BR72A103KA01L)
C107  ValueDisplayed: 0.01µF  [0805_HV]  (hidden comment: GRM21BR72A103KA01L)
C108  ValueDisplayed: 0.047µF  [0603]  (hidden comment: GCM188R71E473KA37D)
D100  1N4148W-7-F  [SOD-123]
D101  value 68V  [SOT-23]  (hidden comment: BZX84C68LT1G)
D102  1N4148W-7-F  [SOD-123]
D103  SMAJ78CA  value 78V  [SMA]
D104  5.0SMDJ78A  value 78V  [SMC]
D105  value 68V  [SOT-23]  (hidden comment: BZX84C68LT1G)
D106  BAS516,115  [SOD-523]
D107  BAS516,115  [SOD-523]
Q100  IPB180N10S402ATMA1  [DDPAK-7]
Q101  IPB180N10S402ATMA1  [DDPAK-7]
Q102  IPB180N10S402ATMA1  [DDPAK-7]
Q103  IPB180N10S402ATMA1  [DDPAK-7]
Q104  MMBTA06-7-F  [SOT-23]
R100  ValueDisplayed: 100k  [0603]  (hidden comment: RC0603FR-07100KL)
R101  ValueDisplayed: 1.00k  [0603]  (hidden comment: RC0603FR-071KL)
R103  ValueDisplayed: 2.87k  [0603]  (hidden comment: RC0603FR-072K87L)
R104  ValueDisplayed: 20.5k  [0603]  (hidden comment: RC0603FR-0720K5L)
R105  ValueDisplayed: 2.00k  [0603]  (hidden comment: RC0603FR-072KL)
R106  ValueDisplayed: 330k  [0603]  (hidden comment: RC0603FR-07330KL)
R107  ValueDisplayed: 2.70k  [0603]  (hidden comment: RC0603FR-072K7L)
R108  ValueDisplayed: 100k  [0603]  (hidden comment: RC0603FR-07100KL)
R109  ValueDisplayed: 0  [0603]  (hidden comment: RC0603JR-070RL)
R110  ValueDisplayed: 0  [0603]  (hidden comment: RC0603JR-070RL)
TP100  TESTPOINT  [TP_60MIL-SMT]  (value not drawn)  (no BOM)
U100  LM5060Q1MMX/NOPB  [MUB10A_N]

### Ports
EN48, KL40, KL40_M, KL41, KL41_M, P48V, PGND

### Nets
P48V: D104.1(K) D107.2(A) Q101.4(D) Q103.4(D) R104.1 R109.1 ; port P48V
PGND: C103.2 C104.2 C105.2 C106.2 C107.2 C108.2 D101.1(A) D103.2 D104.2(A) D105.1(A) R106.2 R107.1 R108.1 R110.1 U100.6(GND) ; port KL41, port PGND  [project net GND]
EN48: U100.5(EN) ; port EN48
KL40: C100.1 C101.1 C102.1 D103.1 D106.2(A) Q100.4(D) Q102.4(D) R100.2 R101.2 R103.2 ; port KL40
KL40_M: R109.2 ; port KL40_M
KL41_M: R110.2 ; port KL41_M
NetC100_2: C100.2 C103.1
NetC101_2: C101.2 C104.1
NetC102_2: C102.2 C105.1
NetC106_1: C106.1 D100.2(A) Q100.1(G) Q101.1(G) Q102.1(G) Q103.1(G) Q104.3(C) R105.1
NetC107_1: C107.1 D105.3(K) D106.1(K) D107.1(K) U100.2(VIN)
NetC108_1: C108.1 U100.7(TIMER)
NetD100_1: D100.1(K) R105.2 U100.10(GATE)
NetD101_3: D101.3(K) R103.1 U100.1(SEN)
NetD102_1: D102.1(K) Q104.1(B) R106.1
NetD102_2: D102.2(A) Q100.2(S) Q100.3(S) Q100.5(S) Q100.6(S) Q100.7(S) Q101.2(S) Q101.3(S) Q101.5(S) Q101.6(S) Q101.7(S) Q102.2(S) Q102.3(S) Q102.5(S) Q102.6(S) Q102.7(S) Q103.2(S) Q103.3(S) Q103.5(S) Q103.6(S) Q103.7(S) Q104.2(E)
NetR100_1: R100.1 R107.2 U100.3(OVP)
NetR101_1: R101.1 R108.2 U100.4(UVLO)
NetR104_2: R104.2 U100.9(OUT)
NetTP100_1: TP100.1 U100.8(nPGD)

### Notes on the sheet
- E1 to E2 Change in SCM. For E1 layout D106 takes place of formal R102 and D107 is hand-wired
- Rdson = typ. 2mOhm
- (near R103) Ilim = typ. 60 A
- UVLO = 0 V
- OVP = 76.07 V
- (near C106) Soft-start
- (near R109) Kelvin connection, check the PCB layout

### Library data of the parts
C100 C103 = CGA6M2X7R2A474K200AA: CAP, CERM, 0.47 µF, 100 V, +/- 10%, X7R, AEC-Q200 Grade 1, 1210; Manufacturer: TDK; Polarized: N; CompType: Capacitor; Value: 0.47uF; U/M: EA; Cap_F: 0.00000047; Tolerance_%: 10; ESR_ohm: 0.009164; Value1: 0.009164 ohm; VDC_V: 100; Value2: 100V; IRMS_A: 2.43674; TaMin_C: -55; TaMax_C: 125; Cap_Case: 1210_220; SizeArea_mm2: 8; SizeAreaWB_mm2: 14.7; SizeX_mm: 3.2; SizeY_mm: 2.5; SizeZ_mm: 2.2; AEC Category: Q200; AEC Qualified: Y; AEC Grade: 1
C101 C102 C104 C105 = CGA6P3X7S1H106K250AB: CAP, CERM, 10 µF, 50 V, +/- 10%, X7S, AEC-Q200 Grade 1, 1210; Manufacturer: TDK; Polarized: N; CompType: Capacitor; Value: 10uF; U/M: EA; Cap_F: 0.00001; Tolerance_%: 10; ESR_ohm: 0.002827; Value1: 0.002827 ohm; VDC_V: 50; Value2: 50V; IRMS_A: 4.37286; TaMin_C: -55; TaMax_C: 125; SizeArea_mm2: 8; SizeAreaWB_mm2: 14.7; SizeX_mm: 3.2; SizeY_mm: 2.5; SizeZ_mm: 2.8; AEC Category: Q200; AEC Qualified: Y; AEC Grade: 1
C106 C107 = GRM21BR72A103KA01L: CAP, CERM, 0.01 µF, 100 V, +/- 10%, X7R, 0805; Manufacturer: MuRata; Polarized: N; CompType: Capacitor; Value: 0.01uF; U/M: EA; Cap_F: 0.00000001; Tolerance_%: 10; Value1: Unknown; VDC_V: 100; Value2: 100V; TaMin_C: -55; TaMax_C: 125; Cap_Case: 0805; AEC Category: Q200; SizeArea_mm2: 2.5; SizeAreaWB_mm2: 6.75; SizeX_mm: 2; SizeY_mm: 1.25; SizeZ_mm: 1.45
C108 = GCM188R71E473KA37D: CAP, CERM, 0.047 µF, 25 V, +/- 10%, X7R, AEC-Q200 Grade 1, 0603; Manufacturer: MuRata; Polarized: N; CompType: Capacitor; Value: 0.047uF; U/M: EA; Cap_F: 0.000000047; Tolerance_%: 10; Value1: Unknown; VDC_V: 25; Value2: 25V; TaMin_C: -55; TaMax_C: 125; AEC Category: Q200; AEC Qualified: Y; AEC Grade: 1; SizeArea_mm2: 1.28; SizeAreaWB_mm2: 4.68; SizeX_mm: 1.6; SizeY_mm: 0.8
D100 D102 = 1N4148W-7-F: Diode, Ultrafast, 100 V, 0.15 A, SOD-123; Manufacturer: Diodes Inc.; U/M: EA; Vf_V: 1.25; Value: 100V; Value1: 0.15A; Value2: 1.25V; Io_A: 0.15; Vr_V: 100; TJmax_C: 150; SizeAreaWB_mm2: 13.095; SizeArea_mm2: 6.545; SizeX_mm: 3.85; SizeY_mm: 1.7; SizeZ_mm: 1.35; AEC Category: Q101
D101 D105 = BZX84C68LT1G: Diode, Zener, 68 V, 225 mW, SOT-23; Manufacturer: ON Semiconductor; U/M: EA; Power_W: 0.225; Vz_V: 68; Value1: 0.225W; RJA_CperW: 500; SizeAreaWB_mm2: 14; SizeArea_mm2: 7.5; SizeX_mm: 2.5; SizeY_mm: 3; SizeZ_mm: 1.1; AEC Category: Q101; AEC Qualified: N
D103 = SMAJ78CA: Diode, TVS, Bi, 78 V, SMA; Manufacturer: Littelfuse; U/M: EA; Power_W: 3.3; Vr_V: 78; Value1: 3.3W; RJA_CperW: 120; SizeAreaWB_mm2: 37.3428; SizeArea_mm2: 16.3228; SizeX_mm: 5.59; SizeY_mm: 2.92; SizeZ_mm: 2.87; AEC Category: Q101
D104 = 5.0SMDJ78A: Diode, TVS, Uni, 78 V, 126 Vc, SMC; Manufacturer: Littelfuse; U/M: EA; Power_W: 6.5; Vr_V: 78; Value1: 6.5W; RJA_CperW: 75; SizeAreaWB_mm2: 83.2686; SizeArea_mm2: 50.5686; SizeX_mm: 8.13; SizeY_mm: 6.22; SizeZ_mm: 2.6; AEC Category: Q101
D106 D107 = BAS516,115: Diode, Switching, 100 V, 0.25 A, SOD-523; Manufacturer: NXP Semiconductor; U/M: EA; Vf_V: 1.25; Value: 100V; Value1: 0.25A; Value2: 1.25V; Io_A: 0.25; Vr_V: 100; TJmax_C: 150; SizeAreaWB_mm2: 5.13; SizeArea_mm2: 1.53; SizeX_mm: 1.7; SizeY_mm: 0.9; SizeZ_mm: 0.65; AEC Category: Q101
Q100-Q103 = IPB180N10S402ATMA1: MOSFET, N-CH, 100 V, 180 A, AEC-Q101, DDPAK-7; Manufacturer: Infineon Technologies; Alternate Manufacturer: None; U/M: EA; ChType: N; Value: 100V; VdsMax_V: 100; Value1: ? ohm; Value2: 156 nC; QgTyp_nC: 156; Vgs_V: 20; IdsMax_A: 180; SizeAreaWB_mm2: 209.6992; SizeArea_mm2: 154.8892; SizeX_mm: 15.245; SizeY_mm: 10.16; SizeZ_mm: 4.445; AEC Category: Q101; AEC Qualified: Y; SymbolCreator: a0412235
Q104 = MMBTA06-7-F, Diodes Inc.: Transistor, NPN, 80 V, 0.5 A, SOT-23; CompType: BJT; PNP: 0; NPN: 1; Vceo_V: 80; Vcesat1_V: 0.25; Value: 80 V; IcRated_A: 0.5; Value1: 0.5 A; TaMin_C: -55; TaMax_C: 150; U/M: EA; AEC Category: Q101
R100 R108 = RC0603FR-07100KL: RES, 100 k, 1%, 0.1 W, 0603; Manufacturer: Yageo America; CompType: Resistor; Value: 100k; Res_ohm: 100000; Tolerance_%: 1; Power_W: 0.1; Value2: 0.1W; VDC_V: 150; TempCo: 200 ppm/C; EIA_Code: E96; U/M: EA; AEC Category: Q200; SizeArea_mm2: 1.28; SizeX_mm: 1.6; SizeY_mm: 0.8
R101 = RC0603FR-071KL: RES, 1.00 k, 1%, 0.1 W, 0603; Manufacturer: Yageo America; CompType: Resistor; Value: 1.00k; Res_ohm: 1000; Value_Code: 1k00; Tolerance_%: 1; Power_W: 0.1; Value2: 0.1W; VDC_V: 150; TempCo: 200 ppm/C; EIA_Code: E96; U/M: EA; AEC Category: Q200; SizeArea_mm2: 1.28; SizeX_mm: 1.6; SizeY_mm: 0.8
R103 = RC0603FR-072K87L: RES, 2.87 k, 1%, 0.1 W, 0603; Manufacturer: Yageo America; CompType: Resistor; Value: 2.87k; Res_ohm: 2870; Value_Code: 2k87; Tolerance_%: 1; Power_W: 0.1; Value2: 0.1W; VDC_V: 150; TempCo: 200 ppm/C; EIA_Code: E96; U/M: EA; AEC Category: Q200; SizeArea_mm2: 1.28; SizeX_mm: 1.6; SizeY_mm: 0.8
R104 = RC0603FR-0720K5L: RES, 20.5 k, 1%, 0.1 W, 0603; Manufacturer: Yageo America; CompType: Resistor; Value: 20.5k; Res_ohm: 20500; Value_Code: 20k5; Tolerance_%: 1; Power_W: 0.1; Value2: 0.1W; VDC_V: 150; TempCo: 200 ppm/C; EIA_Code: E96; U/M: EA; AEC Category: Q200; SizeArea_mm2: 1.28; SizeX_mm: 1.6; SizeY_mm: 0.8
R105 = RC0603FR-072KL: RES, 2.00 k, 1%, 0.1 W, 0603; Manufacturer: Yageo America; CompType: Resistor; Value: 2.00k; Res_ohm: 2000; Value_Code: 2k00; Tolerance_%: 1; Power_W: 0.1; Value2: 0.1W; VDC_V: 150; TempCo: 200 ppm/C; EIA_Code: E96; U/M: EA; AEC Category: Q200; SizeArea_mm2: 1.28; SizeX_mm: 1.6; SizeY_mm: 0.8
R106 = RC0603FR-07330KL: RES, 330 k, 1%, 0.1 W, 0603; Manufacturer: Yageo America; CompType: Resistor; Value: 330k; Res_ohm: 330000; Tolerance_%: 1; Power_W: 0.1; Value2: 0.1W; VDC_V: 150; TempCo: 200 ppm/C; U/M: EA; AEC Category: Q200; SizeArea_mm2: 1.28; SizeX_mm: 1.6; SizeY_mm: 0.8
R107 = RC0603FR-072K7L: RES, 2.70 k, 1%, 0.1 W, 0603; Manufacturer: Yageo America; CompType: Resistor; Value: 2.70k; Res_ohm: 2700; Value_Code: 2k70; Tolerance_%: 1; Power_W: 0.1; Value2: 0.1W; VDC_V: 150; TempCo: 200 ppm/C; U/M: EA; AEC Category: Q200; SizeArea_mm2: 1.28; SizeX_mm: 1.6; SizeY_mm: 0.8
R109 R110 = RC0603JR-070RL: RES, 0, 5%, 0.1 W, 0603; Manufacturer: Yageo America; CompType: Resistor; Value: 0; Value_Code: 0000; Tolerance_%: 5; Power_W: 0.1; Value2: 0.1W; VDC_V: 50; TempCo: 200 ppm/C; EIA_Code: E24; U/M: EA; AEC Category: Q200; SizeArea_mm2: 1.28; SizeX_mm: 1.6; SizeY_mm: 0.8; SizeZ_mm: 1
TP100 = TESTPOINT: TEST POINT.  No entry in BOM.
U100 = LM5060Q1MMX/NOPB: High-Side Protection Controller with Low Quiescent Current, 10-pin MSOP, Pb-Free; Manufacturer: Texas Instruments; PackageTopMarking: ZXTT*SZAB; PowerWise: N; CompType: Switcher

## Sheet TIDA-01168_12V_Brk.SchDoc: 12-V Circuit Breaker
size 431 x 279 mm; Date: Not shown in title block; ApprovedBy: Not shown in title block; CheckedBy: Not shown in title block; Author: Not shown in title block; CompanyName: Not shown in title block; Engineer: Not shown in title block; Organization: Not shown in title block; Address1: Not shown in title block; Address2: Not shown in title block; Address3: Not shown in title block; Address4: Not shown in title block; DocumentNumber: 5; Revision: Use project parameter SCH_Rev; SheetNumber: 5; SheetTotal: 11; PageSetup: Record=PageOptions¦CenterHorizontal=True¦CenterVertical=True¦PrintScale=0.62¦XCorrection=1.00¦YCorrection=1.00¦PrintKind=0¦BorderSize=5000000¦LeftOffset=0¦BottomOffset=0¦Orientation=2¦PaperLength=1000¦PaperWidth=1000¦Scale=100¦PaperSource=15¦PrintQuality=600¦MediaType=1¦DitherType=10¦PrintScaleMode=1¦PaperKind=Letter
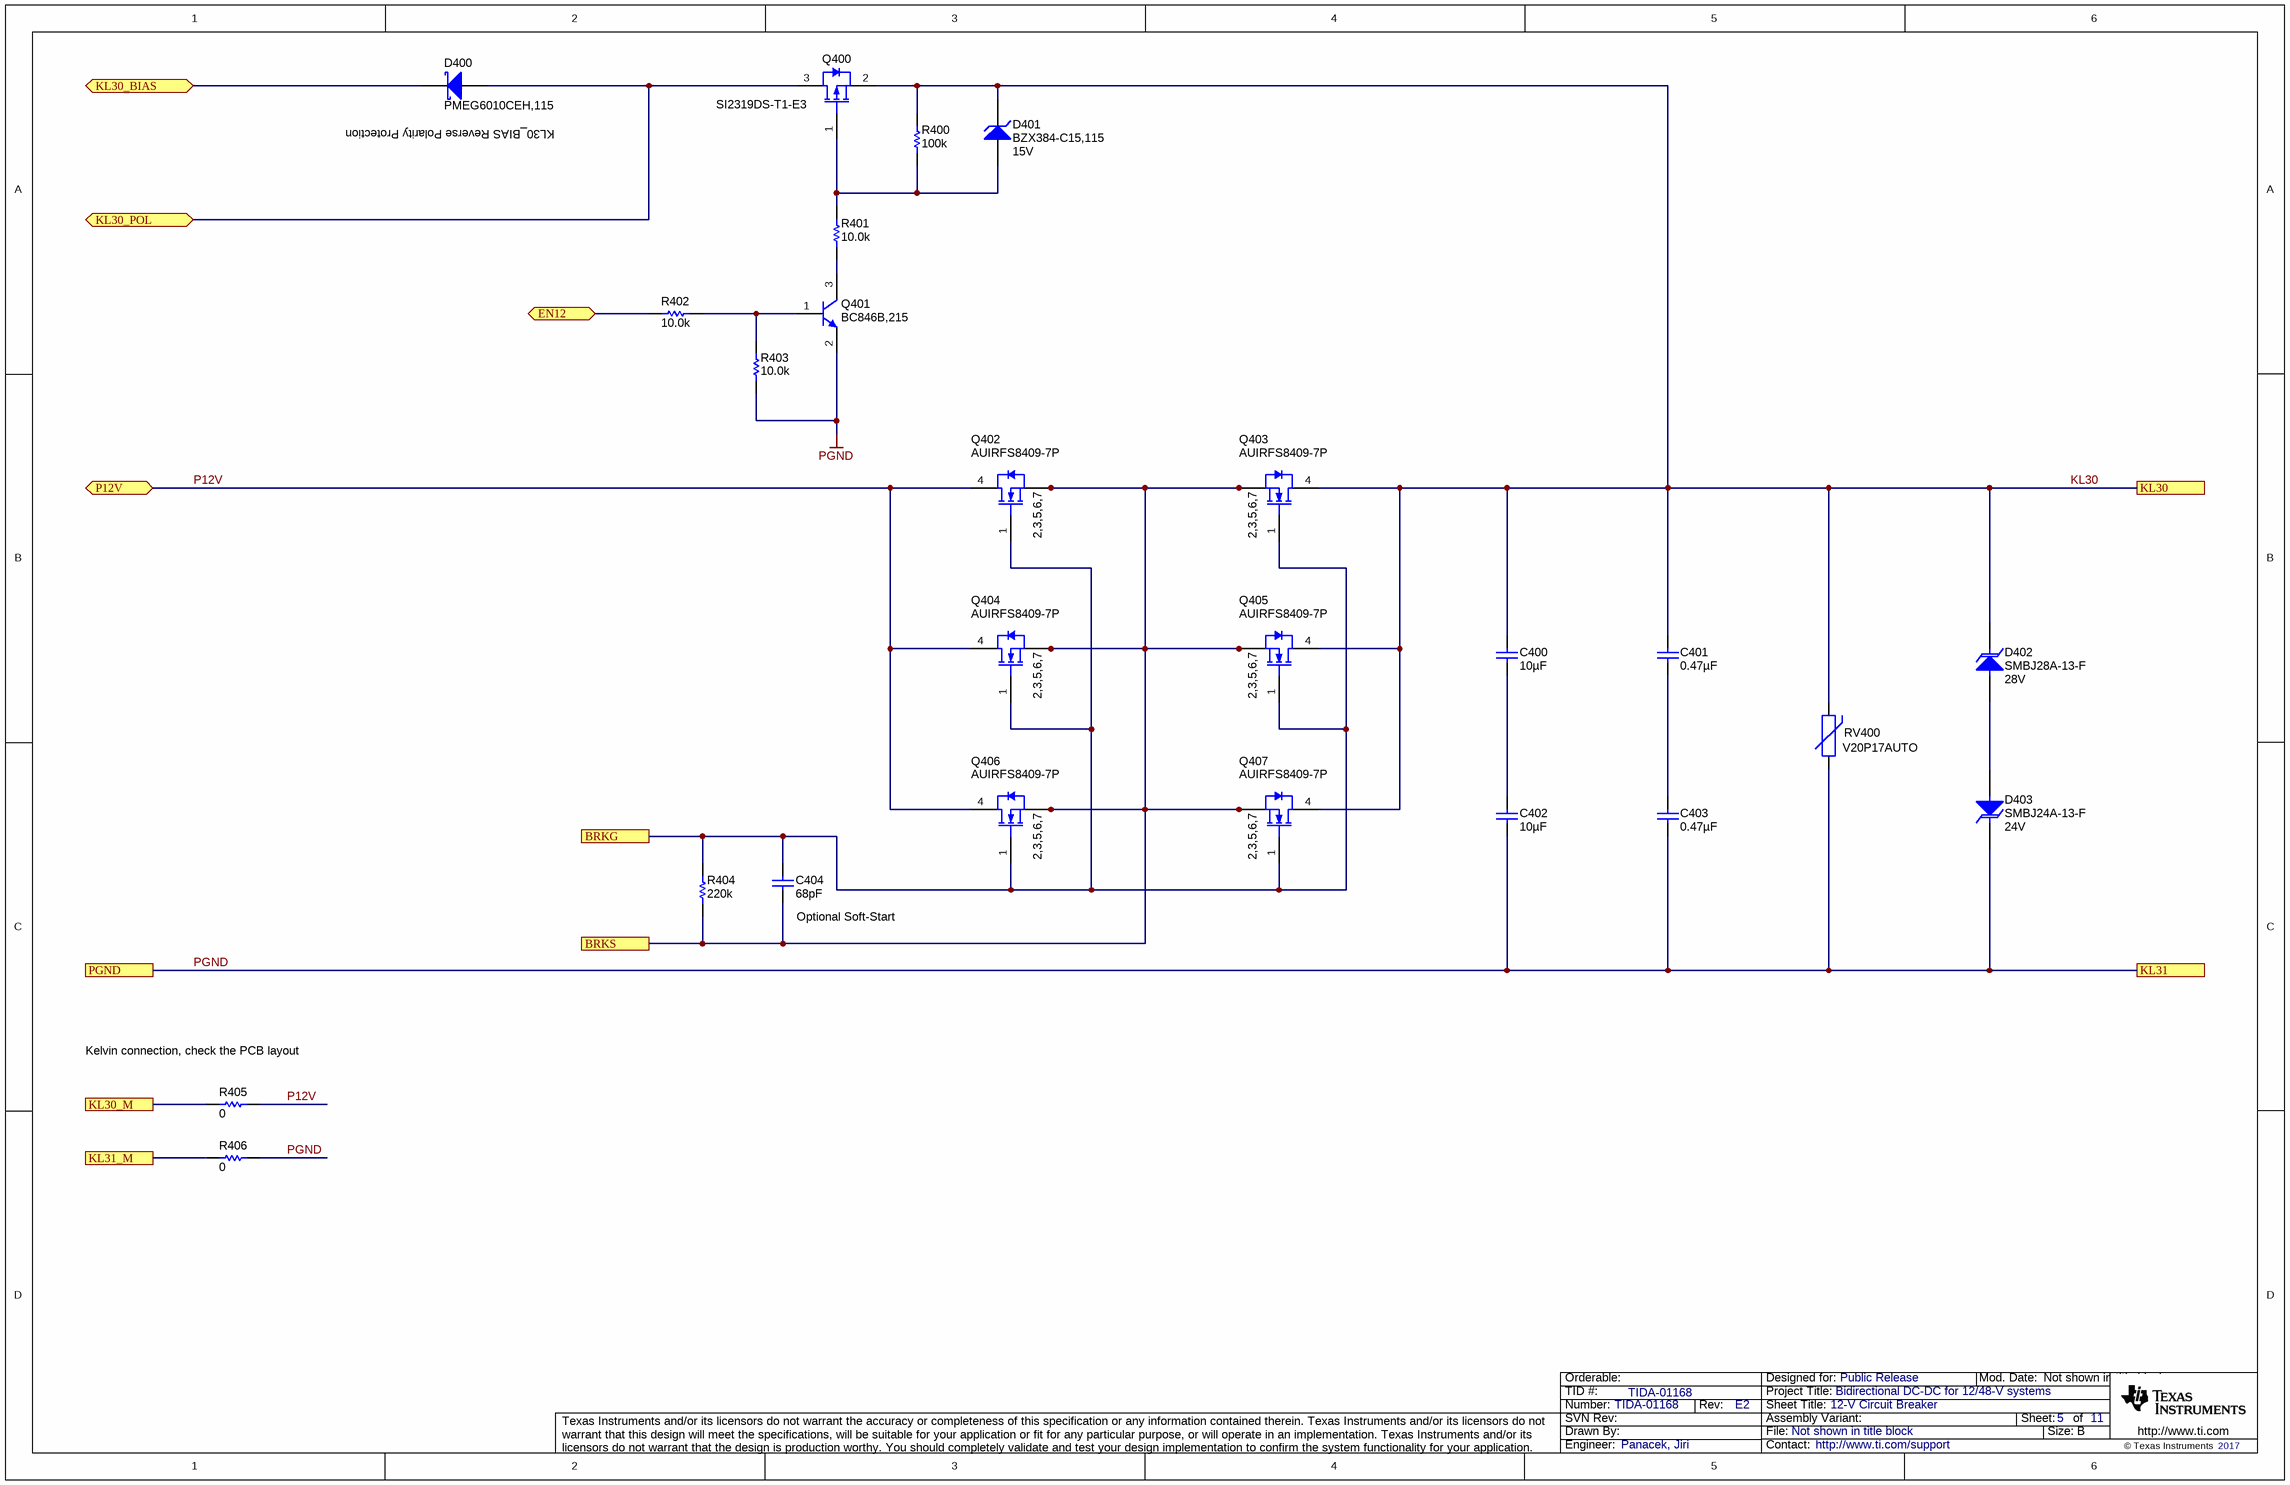
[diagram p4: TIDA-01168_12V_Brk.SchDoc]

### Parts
C400  ValueDisplayed: 10µF  [1210_280]  (hidden comment: CGA6P3X7S1H106K250AB)
C401  ValueDisplayed: 0.47µF  [1210_220L]  (hidden comment: CGA6M2X7R2A474K200AA)
C402  ValueDisplayed: 10µF  [1210_280]  (hidden comment: CGA6P3X7S1H106K250AB)
C403  ValueDisplayed: 0.47µF  [1210_220L]  (hidden comment: CGA6M2X7R2A474K200AA)
C404  ValueDisplayed: 68pF  [0603]  (hidden comment: GCM1885C1H680JA16D)
D400  PMEG6010CEH,115  [SOD-123F]
D401  BZX384-C15,115  value 15V  [SOD-323]
D402  SMBJ28A-13-F  value 28V  [SMB]
D403  SMBJ24A-13-F  value 24V  [SMB]
Q400  SI2319DS-T1-E3  [SOT-23]
Q401  BC846B,215  [SOT-23]
Q402  AUIRFS8409-7P  [DDPAK-7]
Q403  AUIRFS8409-7P  [DDPAK-7]
Q404  AUIRFS8409-7P  [DDPAK-7]
Q405  AUIRFS8409-7P  [DDPAK-7]
Q406  AUIRFS8409-7P  [DDPAK-7]
Q407  AUIRFS8409-7P  [DDPAK-7]
R400  ValueDisplayed: 100k  [0603]  (hidden comment: RC0603FR-07100KL)
R401  ValueDisplayed: 10.0k  [0603]  (hidden comment: RC0603FR-0710KL)
R402  ValueDisplayed: 10.0k  [0603]  (hidden comment: RC0603FR-0710KL)
R403  ValueDisplayed: 10.0k  [0603]  (hidden comment: RC0603FR-0710KL)
R404  ValueDisplayed: 220k  [0603]  (hidden comment: RC0603FR-07220KL)
R405  ValueDisplayed: 0  [0603]  (hidden comment: RC0603JR-070RL)
R406  ValueDisplayed: 0  [0603]  (hidden comment: RC0603JR-070RL)
RV400  V20P17AUTO  [Littelfuse_V20P17AUTO]

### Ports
BRKG, BRKS, EN12, KL30, KL30_BIAS, KL30_M, KL30_POL, KL31, KL31_M, P12V, PGND

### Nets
KL30_BIAS: D400.1(K) ; port KL30_BIAS
P12V: Q402.4(D) Q404.4(D) Q406.4(D) R405.1 ; port P12V  [project net CS1B_A]
PGND: C402.2 C403.2 D403.1(K) Q401.2(E) R403.1 R406.1 RV400.1 ; port KL31, port PGND  [project net GND]
BRKG: C404.1 Q402.1(G) Q403.1(G) Q404.1(G) Q405.1(G) Q406.1(G) Q407.1(G) R404.1 ; port BRKG
BRKS: C404.2 Q402.2(S) Q402.3(S) Q402.5(S) Q402.6(S) Q402.7(S) Q403.2(S) Q403.3(S) Q403.5(S) Q403.6(S) Q403.7(S) Q404.2(S) Q404.3(S) Q404.5(S) Q404.6(S) Q404.7(S) Q405.2(S) Q405.3(S) Q405.5(S) Q405.6(S) Q405.7(S) Q406.2(S) Q406.3(S) Q406.5(S) Q406.6(S) Q406.7(S) Q407.2(S) Q407.3(S) Q407.5(S) Q407.6(S) Q407.7(S) R404.2 ; port BRKS
EN12: R402.1 ; port EN12
KL30: C400.1 C401.1 D401.1(K) D402.1(K) Q400.2(S) Q403.4(D) Q405.4(D) Q407.4(D) R400.2 RV400.2 ; port KL30
KL30_M: R405.2 ; port KL30_M
KL30_POL: D400.2(A) Q400.3(D) ; port KL30_POL
KL31_M: R406.2 ; port KL31_M
NetC400_2: C400.2 C402.1
NetC401_2: C401.2 C403.1
NetD401_2: D401.2(A) Q400.1(G) R400.1 R401.2
NetD402_2: D402.2(A) D403.2(A)
NetQ401_1: Q401.1(B) R402.2 R403.2
NetQ401_3: Q401.3(C) R401.1

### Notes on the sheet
- (near D400) KL30_BIAS Reverse Polarity Protection
- (near C404) Optional Soft-Start
- (near R405) Kelvin connection, check the PCB layout

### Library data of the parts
C400 C402 = CGA6P3X7S1H106K250AB: as C101 on sheet TIDA-01168_48V_Brk
C401 C403 = CGA6M2X7R2A474K200AA: as C100 on sheet TIDA-01168_48V_Brk
C404 = GCM1885C1H680JA16D: CAP, CERM, 68 pF, 50 V, +/- 5%, C0G/NP0, AEC-Q200 Grade 1, 0603; Manufacturer: MuRata; Polarized: N; CompType: Capacitor; Value: 68pF; U/M: EA; Cap_F: 0.000000000068; Tolerance_%: 5; Value1: Unknown; VDC_V: 50; Value2: 50V; TaMin_C: -55; TaMax_C: 125; AEC Category: Q200; AEC Qualified: Y; AEC Grade: 1
D400 = PMEG6010CEH,115: Diode, Schottky, 60 V, 1 A, SOD-123F; Manufacturer: NXP Semiconductor; U/M: EA; Vf_V: 0.57; Value: 60V; Value1: 1A; Value2: 0.57V; Io_A: 1; Vr_V: 60; TJmax_C: 150; SizeAreaWB_mm2: 11.7; SizeArea_mm2: 5.6; SizeX_mm: 3.5; SizeY_mm: 1.6; SizeZ_mm: 1.1; AEC Category: Q101
D401 = BZX384-C15,115: Diode, Zener, 15 V, 300 mW, SOD-323; Manufacturer: NXP Semiconductor; U/M: EA; Value1: 0.3W; AEC Category: Q101; SymbolCreator: a0412235; Power_W: 0.3; Vz_V: 15; RJA_CperW: 415; SizeAreaWB_mm2: 8.695; SizeArea_mm2: 3.645; SizeX_mm: 2.7; SizeY_mm: 1.35; SizeZ_mm: 1
D402 = SMBJ28A-13-F: Diode, TVS, Uni, 28 V, 600 W, SMB; Manufacturer: Diodes Inc.; U/M: EA; Power_W: 5; Vr_V: 28; Value1: 5W; SizeAreaWB_mm2: 44.156; SizeArea_mm2: 21.336; SizeX_mm: 5.6; SizeY_mm: 3.81; SizeZ_mm: 2.6; AEC Category: Q101
D403 = SMBJ24A-13-F: Diode, TVS, Uni, 24 V, 600 W, SMB; Manufacturer: Diodes Inc.; U/M: EA; Power_W: 5; Vr_V: 24; Value1: 5W; SizeAreaWB_mm2: 44.156; SizeArea_mm2: 21.336; SizeX_mm: 5.6; SizeY_mm: 3.81; SizeZ_mm: 2.6; AEC Category: Q101
Q400 = SI2319DS-T1-E3: MOSFET, P-CH, -40 V, -2.3 A, SOT-23; Manufacturer: Vishay-Siliconix; Alternate Manufacturer: None; U/M: EA; ChType: P; Value: -40V; Value1: 0.13 ohm; Rdson45_ohm: 0.13; Value2: 11.3 nC; QgTyp_nC: 11.3; Vgs_V: -20; SizeAreaWB_mm2: 14; SizeArea_mm2: 7.5; SizeX_mm: 2.5; SizeY_mm: 3; SizeZ_mm: 1.1; AEC Category: Q101
Q401 = BC846B,215, NXP Semiconductor: Transistor, NPN, 65 V, 0.1 A, SOT-23; CompType: BJT; PNP: 0; NPN: 1; Vceo_V: 65; Vcesat1_V: 0.09; Value: 65 V; IcRated_A: 0.1; Value1: 0.1 A; HfeMax: 450; TaMin_C: -65; TaMax_C: 150; U/M: EA; AEC Category: Q101; AEC Qualified: N
Q402-Q407 = AUIRFS8409-7P: MOSFET, N-CH, 40 V, 240 A, AEC-Q101, DDPAK-7; Manufacturer: Infineon Technologies; Alternate Manufacturer: None; U/M: EA; ChType: N; Value: 40V; VdsMax_V: 40; Value1: ? ohm; Value2: 305 nC; QgTyp_nC: 305; Vgs_V: 20; IdsMax_A: 240; SizeAreaWB_mm2: 209.6992; SizeArea_mm2: 154.8892; SizeX_mm: 15.245; SizeY_mm: 10.16; SizeZ_mm: 4.445; AEC Category: Q101; AEC Qualified: Y; SymbolCreator: a0412235
R400 = RC0603FR-07100KL: as R100 on sheet TIDA-01168_48V_Brk
R401-R403 = RC0603FR-0710KL: RES, 10.0 k, 1%, 0.1 W, 0603; Manufacturer: Yageo America; CompType: Resistor; Value: 10.0k; Res_ohm: 10000; Value_Code: 10k0; Tolerance_%: 1; Power_W: 0.1; Value2: 0.1W; VDC_V: 150; TempCo: 200 ppm/C; EIA_Code: E96; U/M: EA; AEC Category: Q200; SizeArea_mm2: 1.28; SizeX_mm: 1.6; SizeY_mm: 0.8
R404 = RC0603FR-07220KL: RES, 220 k, 1%, 0.1 W, 0603; Manufacturer: Yageo America; CompType: Resistor; Value: 220k; Res_ohm: 220000; Tolerance_%: 1; Power_W: 0.1; Value2: 0.1W; VDC_V: 150; TempCo: 200 ppm/C; SizeArea_mm2: 1.28; SizeX_mm: 1.6; SizeY_mm: 0.8; U/M: EA; AEC Category: Q200
R405 R406 = RC0603JR-070RL: as R109 on sheet TIDA-01168_48V_Brk
RV400 = V20P17AUTO: VARISTOR 27V, TH; Manufacturer: Littelfuse; SymbolCreator: a0412235

## Sheet TIDA-01168_Diag.SchDoc: Diagnostics
size 431 x 279 mm; Date: Not shown in title block; ApprovedBy: Not shown in title block; CheckedBy: Not shown in title block; Author: Not shown in title block; CompanyName: Not shown in title block; Engineer: Not shown in title block; Organization: Not shown in title block; Address1: Not shown in title block; Address2: Not shown in title block; Address3: Not shown in title block; Address4: Not shown in title block; DocumentNumber: 9; Revision: Use project parameter SCH_Rev; SheetNumber: 9; SheetTotal: 11; PageSetup: Record=PageOptions¦CenterHorizontal=True¦CenterVertical=True¦PrintScale=1.00¦XCorrection=1.00¦YCorrection=1.00¦PrintKind=0¦BorderSize=5000000¦LeftOffset=0¦BottomOffset=0¦Orientation=2¦PaperLength=1000¦PaperWidth=1000¦Scale=100¦PaperSource=15¦PrintQuality=600¦MediaType=1¦DitherType=10¦PaperKind=Letter¦PrintScaleMode=1
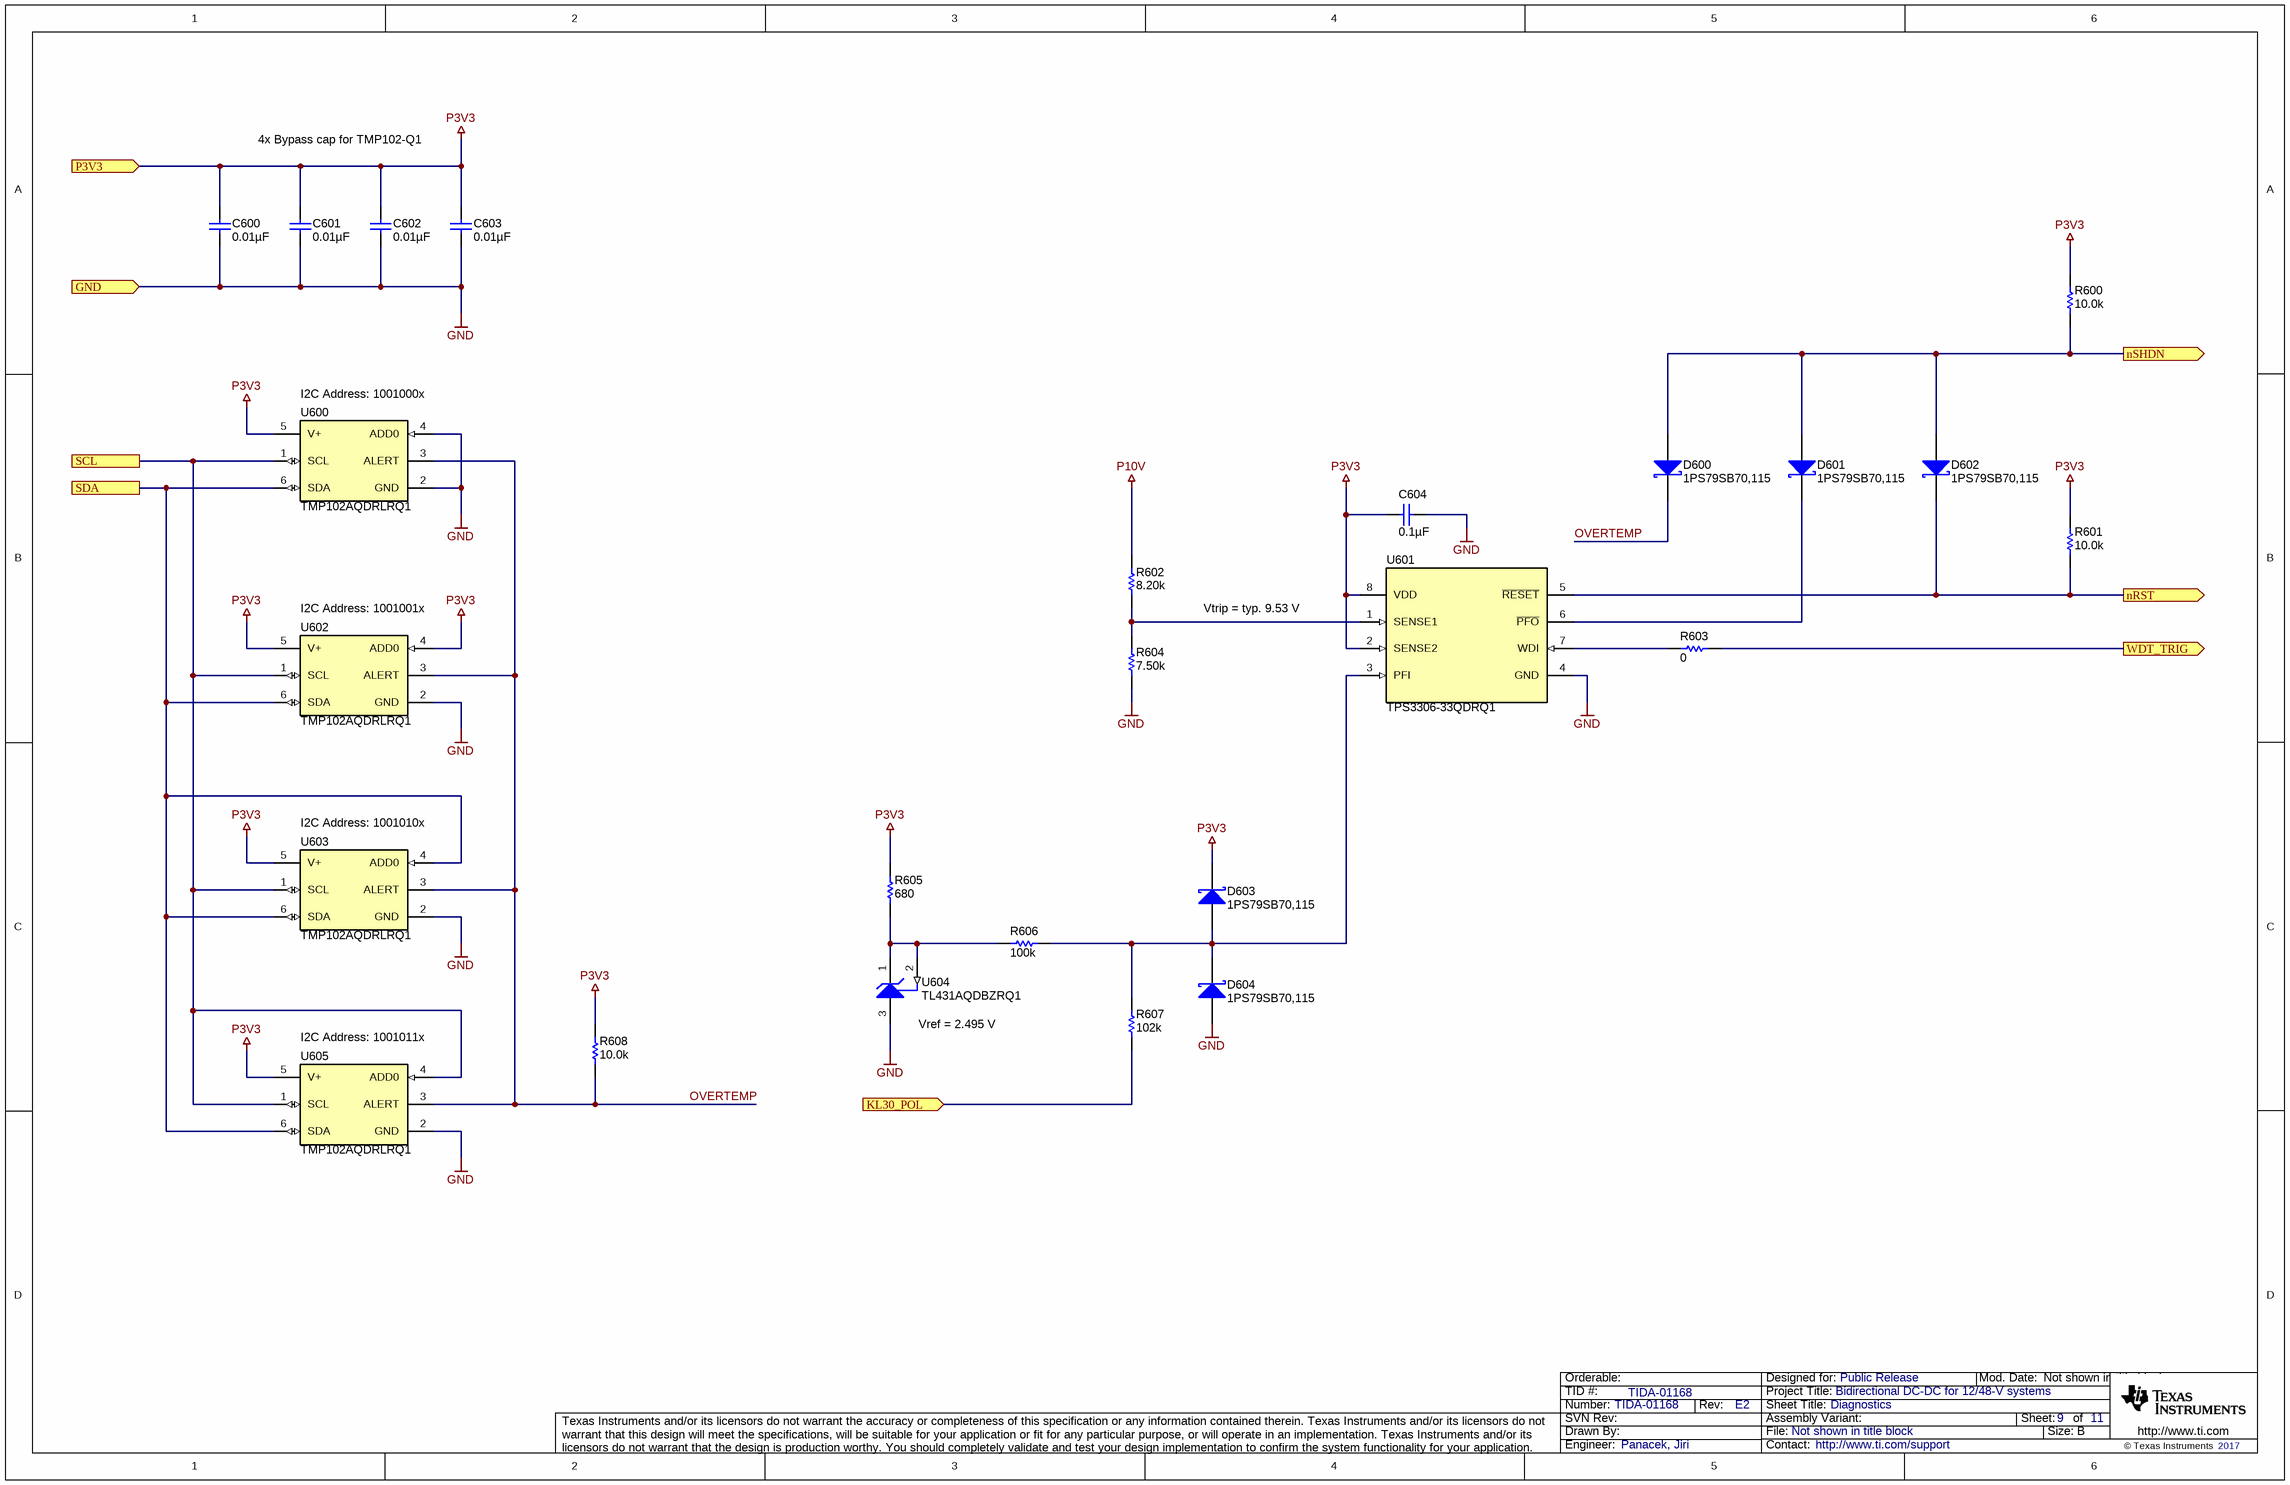
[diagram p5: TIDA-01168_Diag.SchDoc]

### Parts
C600  ValueDisplayed: 0.01µF  [0603]  (hidden comment: GCM188R71H103KA37D)
C601  ValueDisplayed: 0.01µF  [0603]  (hidden comment: GCM188R71H103KA37D)
C602  ValueDisplayed: 0.01µF  [0603]  (hidden comment: GCM188R71H103KA37D)
C603  ValueDisplayed: 0.01µF  [0603]  (hidden comment: GCM188R71H103KA37D)
C604  ValueDisplayed: 0.1µF  [0603]  (hidden comment: GCM188R71H104KA57D)
D600  1PS79SB70,115  [SOD-523]
D601  1PS79SB70,115  [SOD-523]
D602  1PS79SB70,115  [SOD-523]
D603  1PS79SB70,115  [SOD-523]
D604  1PS79SB70,115  [SOD-523]
R600  ValueDisplayed: 10.0k  [0603]  (hidden comment: RC0603FR-0710KL)
R601  ValueDisplayed: 10.0k  [0603]  (hidden comment: RC0603FR-0710KL)
R602  ValueDisplayed: 8.20k  [0603]  (hidden comment: RC0603FR-078K2L)
R603  ValueDisplayed: 0  [0603]  (hidden comment: RC0603JR-070RL)
R604  ValueDisplayed: 7.50k  [0603]  (hidden comment: RC0603FR-077K5L)
R605  ValueDisplayed: 680  [0603]  (hidden comment: RC0603FR-07680RL)
R606  ValueDisplayed: 100k  [0603]  (hidden comment: RC0603FR-07100KL)
R607  ValueDisplayed: 102k  [0603]  (hidden comment: RC0603FR-07102KL)
R608  ValueDisplayed: 10.0k  [0603]  (hidden comment: RC0603FR-0710KL)
U600  TMP102AQDRLRQ1  [DRL0006A]
U601  TPS3306-33QDRQ1  [D0008A_N]
U602  TMP102AQDRLRQ1  [DRL0006A]
U603  TMP102AQDRLRQ1  [DRL0006A]
U604  TL431AQDBZRQ1  [DBZ0003A_N]
U605  TMP102AQDRLRQ1  [DRL0006A]

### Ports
GND, KL30_POL, nRST, nSHDN, P3V3, SCL, SDA, WDT_TRIG

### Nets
GND: C600.2 C601.2 C602.2 C603.2 C604.2 D604.2(A) R604.1 U600.2(GND) U600.4(ADD0) U601.4(GND) U602.2(GND) U603.2(GND) U604.3(ANODE) U605.2(GND) ; port GND
P3V3: C600.1 C601.1 C602.1 C603.1 C604.1 D603.1(K) R600.2 R601.2 R605.1 R608.2 U600.5(V+) U601.2(SENSE2) U601.8(VDD) U602.4(ADD0) U602.5(V+) U603.5(V+) U605.5(V+) ; port P3V3
P10V: R602.2
KL30_POL: R607.2 ; port KL30_POL
nRST: D602.1(K) R601.1 U601.5(~{RESET}) ; port nRST
OVERTEMP: D600.1(K) R608.1 U600.3(ALERT) U602.3(ALERT) U603.3(ALERT) U605.3(ALERT)
SCL: U600.1(SCL) U602.1(SCL) U603.1(SCL) U605.1(SCL) U605.4(ADD0) ; port SCL
SDA: U600.6(SDA) U602.6(SDA) U603.4(ADD0) U603.6(SDA) U605.6(SDA) ; port SDA
UVLO: D600.2(A) D601.2(A) D602.2(A) R600.1 ; port nSHDN
WDT_TRIG: R603.1 ; port WDT_TRIG
NetD601_1: D601.1(K) U601.6(~{PFO})
NetD603_2: D603.2(A) D604.1(K) R606.1 R607.1 U601.3(PFI)
NetR602_1: R602.1 R604.2 U601.1(SENSE1)
NetR603_2: R603.2 U601.7(WDI)
NetR605_2: R605.2 R606.2 U604.1(CATHODE) U604.2(REF)

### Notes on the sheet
- 4x Bypass cap for TMP102-Q1
- (near U600) I2C Address: 1001000x
- (near U602) I2C Address: 1001001x
- Vtrip = typ. 9.53 V
- (near U603) I2C Address: 1001010x
- (near U605) I2C Address: 1001011x
- (near U604) Vref = 2.495 V

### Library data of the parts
C600-C603 = GCM188R71H103KA37D: CAP, CERM, 0.01 µF, 50 V, +/- 10%, X7R, AEC-Q200 Grade 1, 0603; Manufacturer: MuRata; Polarized: N; CompType: Capacitor; Value: 0.01uF; U/M: EA; Cap_F: 0.00000001; Tolerance_%: 10; Value1: Unknown; VDC_V: 50; Value2: 50V; TaMin_C: -55; TaMax_C: 125; SizeArea_mm2: 1.28; SizeAreaWB_mm2: 4.68; SizeX_mm: 1.6; SizeY_mm: 0.8; SizeZ_mm: 1; AEC Category: Q200; AEC Qualified: Y
C604 = GCM188R71H104KA57D: CAP, CERM, 0.1 µF, 50 V, +/- 10%, X7R, 0603; Manufacturer: MuRata; Polarized: N; CompType: Capacitor; Value: 0.1uF; U/M: EA; Cap_F: 0.0000001; Tolerance_%: 10; ESR_ohm: 0.02; Value1: 0.02 ohm; VDC_V: 50; Value2: 50V; IRMS_A: 1.84; TaMin_C: -55; TaMax_C: 125; SizeArea_mm2: 1.28; SizeAreaWB_mm2: 4.68; SizeX_mm: 1.6; SizeY_mm: 0.8; SizeZ_mm: 1; AEC Category: Q200
D600-D604 = 1PS79SB70,115: Diode, Schottky, 70 V, 0.07 A, SOD-523; Manufacturer: NXP Semiconductor; U/M: EA; Vf_V: 0.41; Value: 70V; Value1: 0.07A; Value2: 0.41V; Io_A: 0.07; Vr_V: 70; TJmax_C: 150; AEC Category: Q101
R600 R601 R608 = RC0603FR-0710KL: as R401 on sheet TIDA-01168_12V_Brk
R602 = RC0603FR-078K2L: RES, 8.20 k, 1%, 0.1 W, 0603; Manufacturer: Yageo America; CompType: Resistor; Value: 8.20k; Res_ohm: 8200; Value_Code: 8k20; Tolerance_%: 1; Power_W: 0.1; Value2: 0.1W; VDC_V: 150; TempCo: 200 ppm/C; U/M: EA; AEC Category: Q200; SizeArea_mm2: 1.28; SizeX_mm: 1.6; SizeY_mm: 0.8
R603 = RC0603JR-070RL: as R109 on sheet TIDA-01168_48V_Brk
R604 = RC0603FR-077K5L: RES, 7.50 k, 1%, 0.1 W, 0603; Manufacturer: Yageo America; CompType: Resistor; Value: 7.50k; Res_ohm: 7500; Value_Code: 7k50; Tolerance_%: 1; Power_W: 0.1; Value2: 0.1W; VDC_V: 150; TempCo: 200 ppm/C; EIA_Code: E96; U/M: EA; AEC Category: Q200; SizeArea_mm2: 1.28; SizeX_mm: 1.6; SizeY_mm: 0.8
R605 = RC0603FR-07680RL: RES, 680, 1%, 0.1 W, 0603; Manufacturer: Yageo America; CompType: Resistor; Value: 680; Value_Code: 680R; Tolerance_%: 1; Power_W: 0.1; Value2: 0.1W; VDC_V: 150; TempCo: 200 ppm/C; U/M: EA; AEC Category: Q200; SizeArea_mm2: 1.28; SizeX_mm: 1.6; SizeY_mm: 0.8
R606 = RC0603FR-07100KL: as R100 on sheet TIDA-01168_48V_Brk
R607 = RC0603FR-07102KL: RES, 102 k, 1%, 0.1 W, 0603; Manufacturer: Yageo America; CompType: Resistor; Value: 102k; Res_ohm: 102000; Tolerance_%: 1; Power_W: 0.1; Value2: 0.1W; VDC_V: 150; TempCo: 200 ppm/C; EIA_Code: E96; U/M: EA; AEC Category: Q200; SizeArea_mm2: 1.28; SizeX_mm: 1.6; SizeY_mm: 0.8
U600 U602 U603 U605 = TMP102AQDRLRQ1: Low-Power Digital Temperature Sensor With SMBus and Two-Wire Serial Interface in SOT563, DRL0006A; Manufacturer: Texas Instruments; SymbolCreator: a0799628; SizeArea_mm2: 2.56; SizeAreaWB_mm2: 6.76; SizeX_mm: 1.6; SizeZ_mm: 0.6; CompType: IC; U/M: EA
U601 = TPS3306-33QDRQ1: Dual Processor Supervisory Circuits with power Fail, D0008A; Manufacturer: Texas Instruments; SymbolCreator: Altium; SizeArea_mm2: 30.38; SizeAreaWB_mm2: 56.58; SizeX_mm: 4.9; SizeY_mm: 6.2; SizeZ_mm: 1.75; CompType: IC; U/M: EA
U604 = TL431AQDBZRQ1: Automotive Catalog Adjustable Precision Shunt Regulator, 34 ppm / degC, 100 mA, -40 to 125 degC, 3-pin SOT-23 (DBZ), Green (RoHS & no Sb/Br); Manufacturer: Texas Instruments; Alternate PartNumber: Equivalent; Initial Accuracy @ 25/deg C(%): 1; Iout/Iz(Max)(mA): 100; Min Iz for Regulation(uA): 600; SubFamily: Shunt Voltage Reference; Temp Coeff(Typ)(ppm/ degree C): 34; VO Adj(Max)(V): 36; VO Adj(Min)(V): 2.495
